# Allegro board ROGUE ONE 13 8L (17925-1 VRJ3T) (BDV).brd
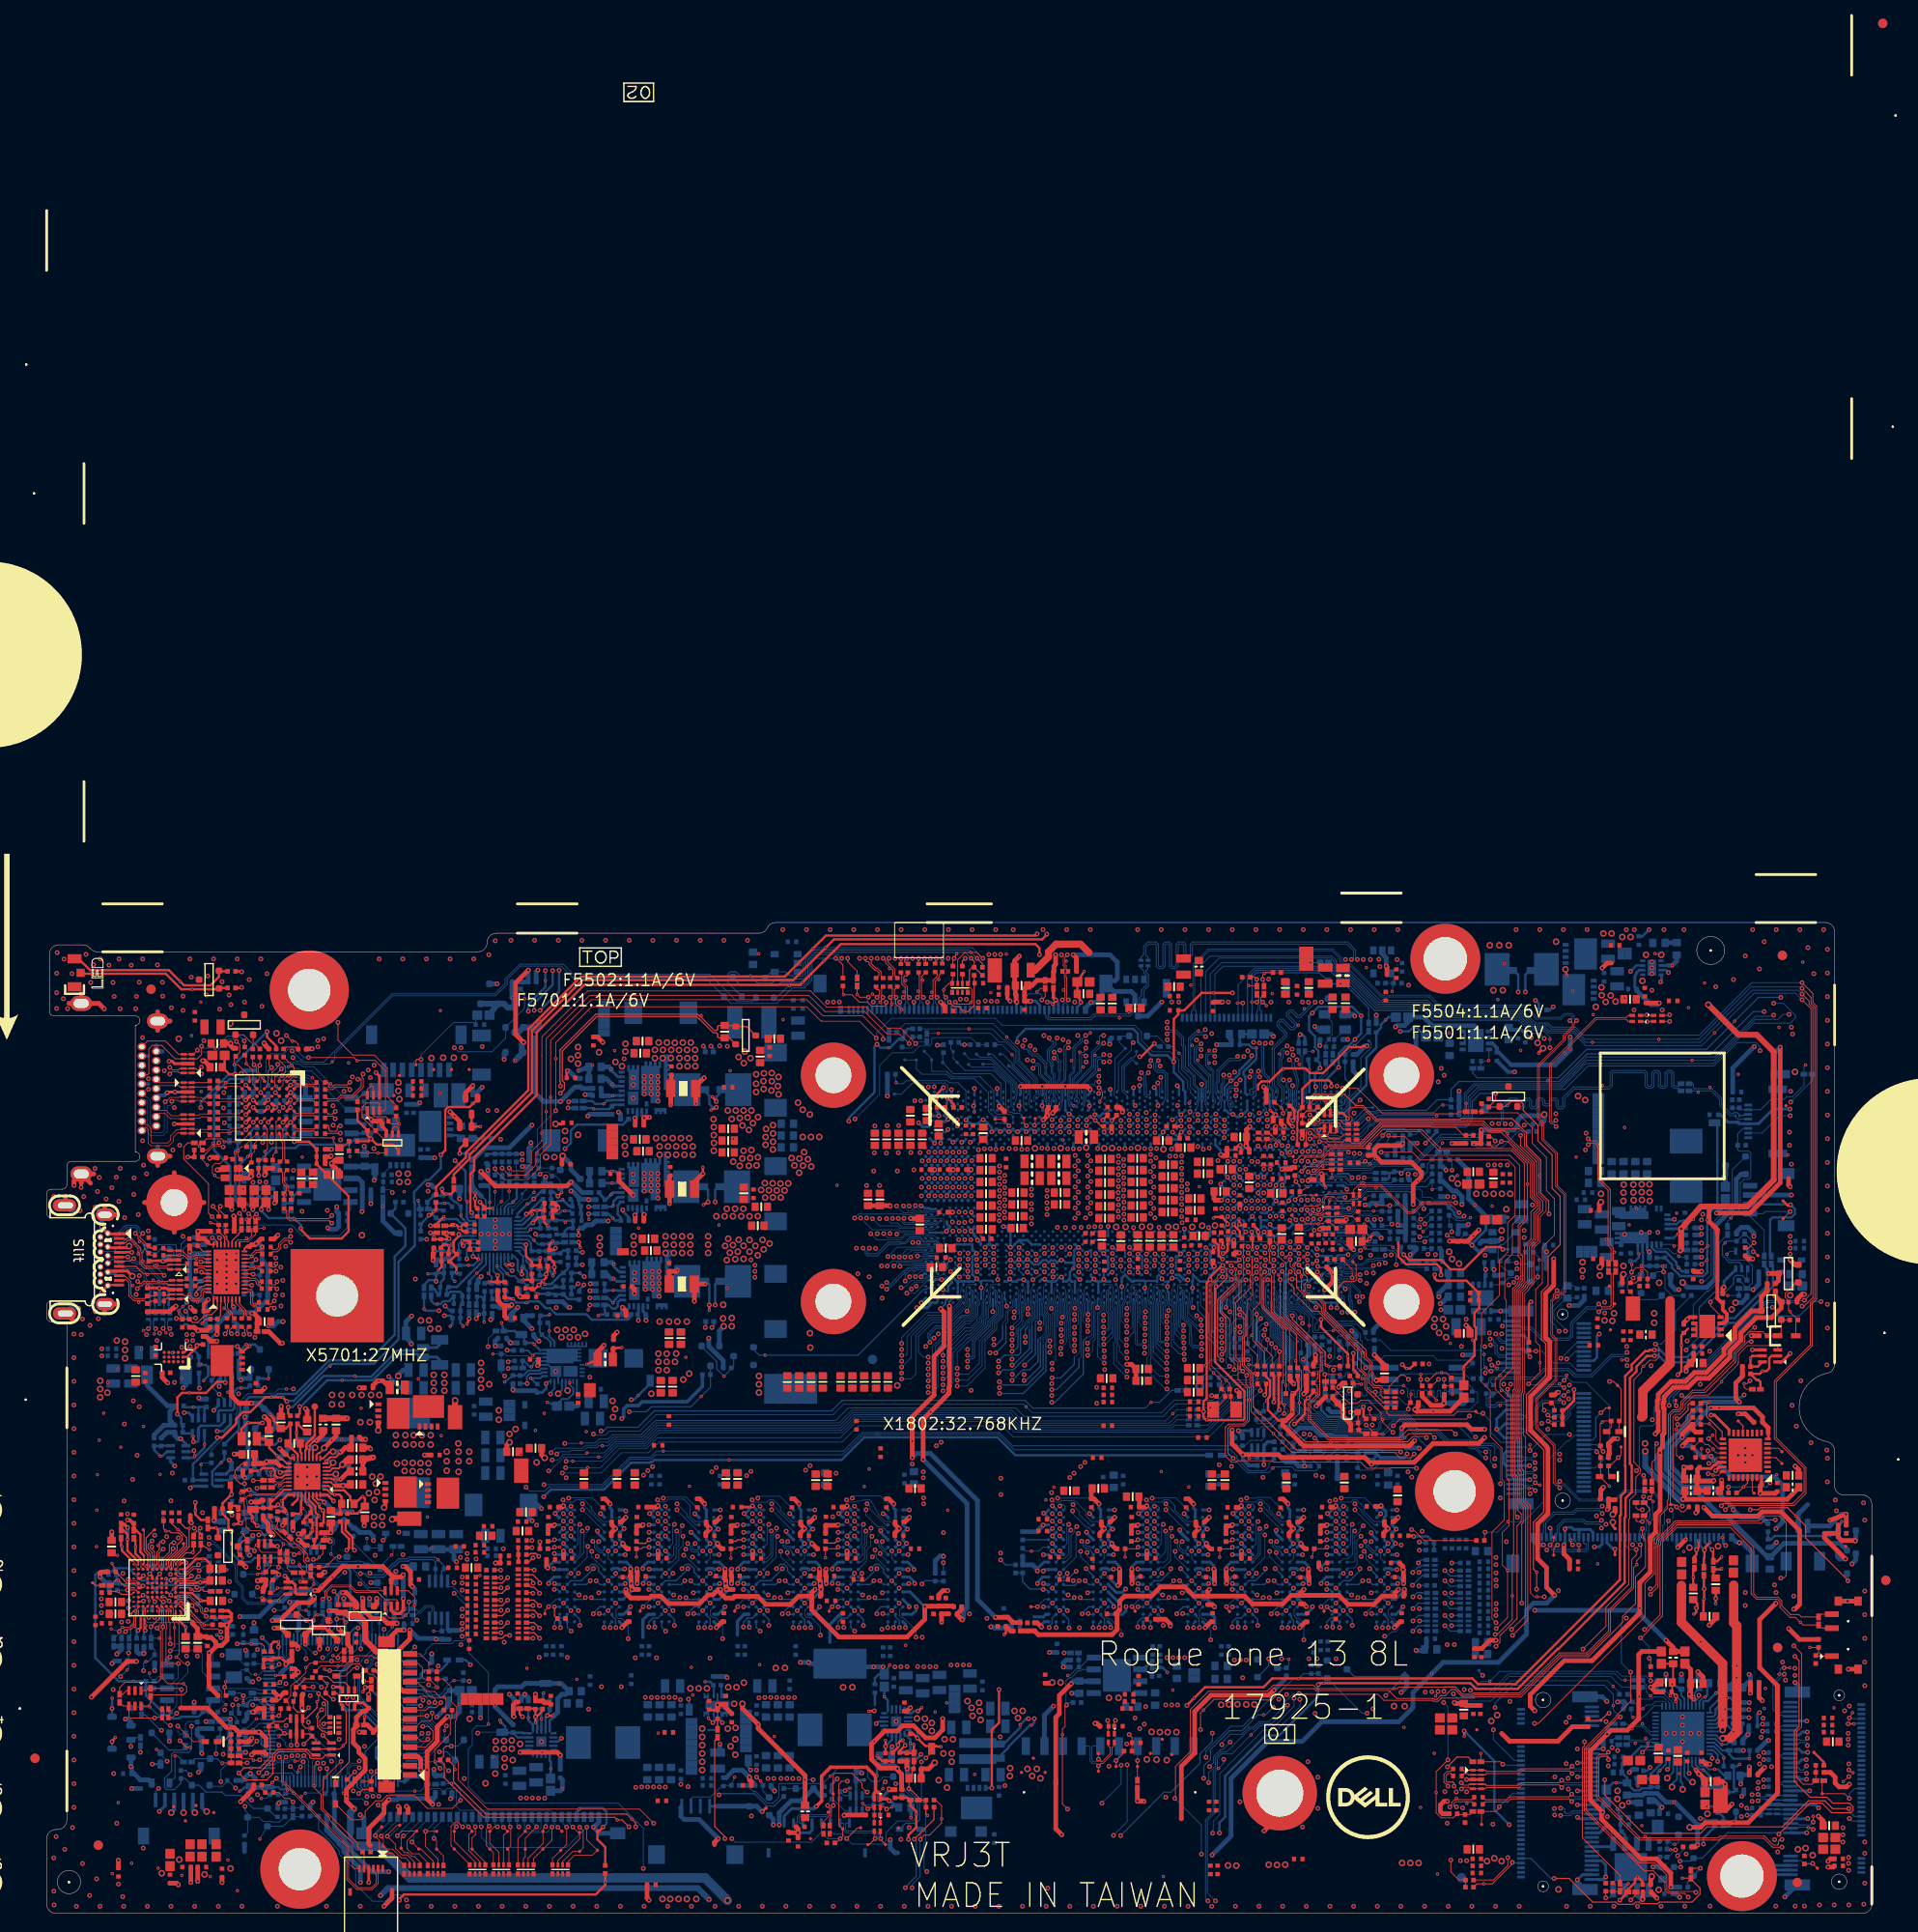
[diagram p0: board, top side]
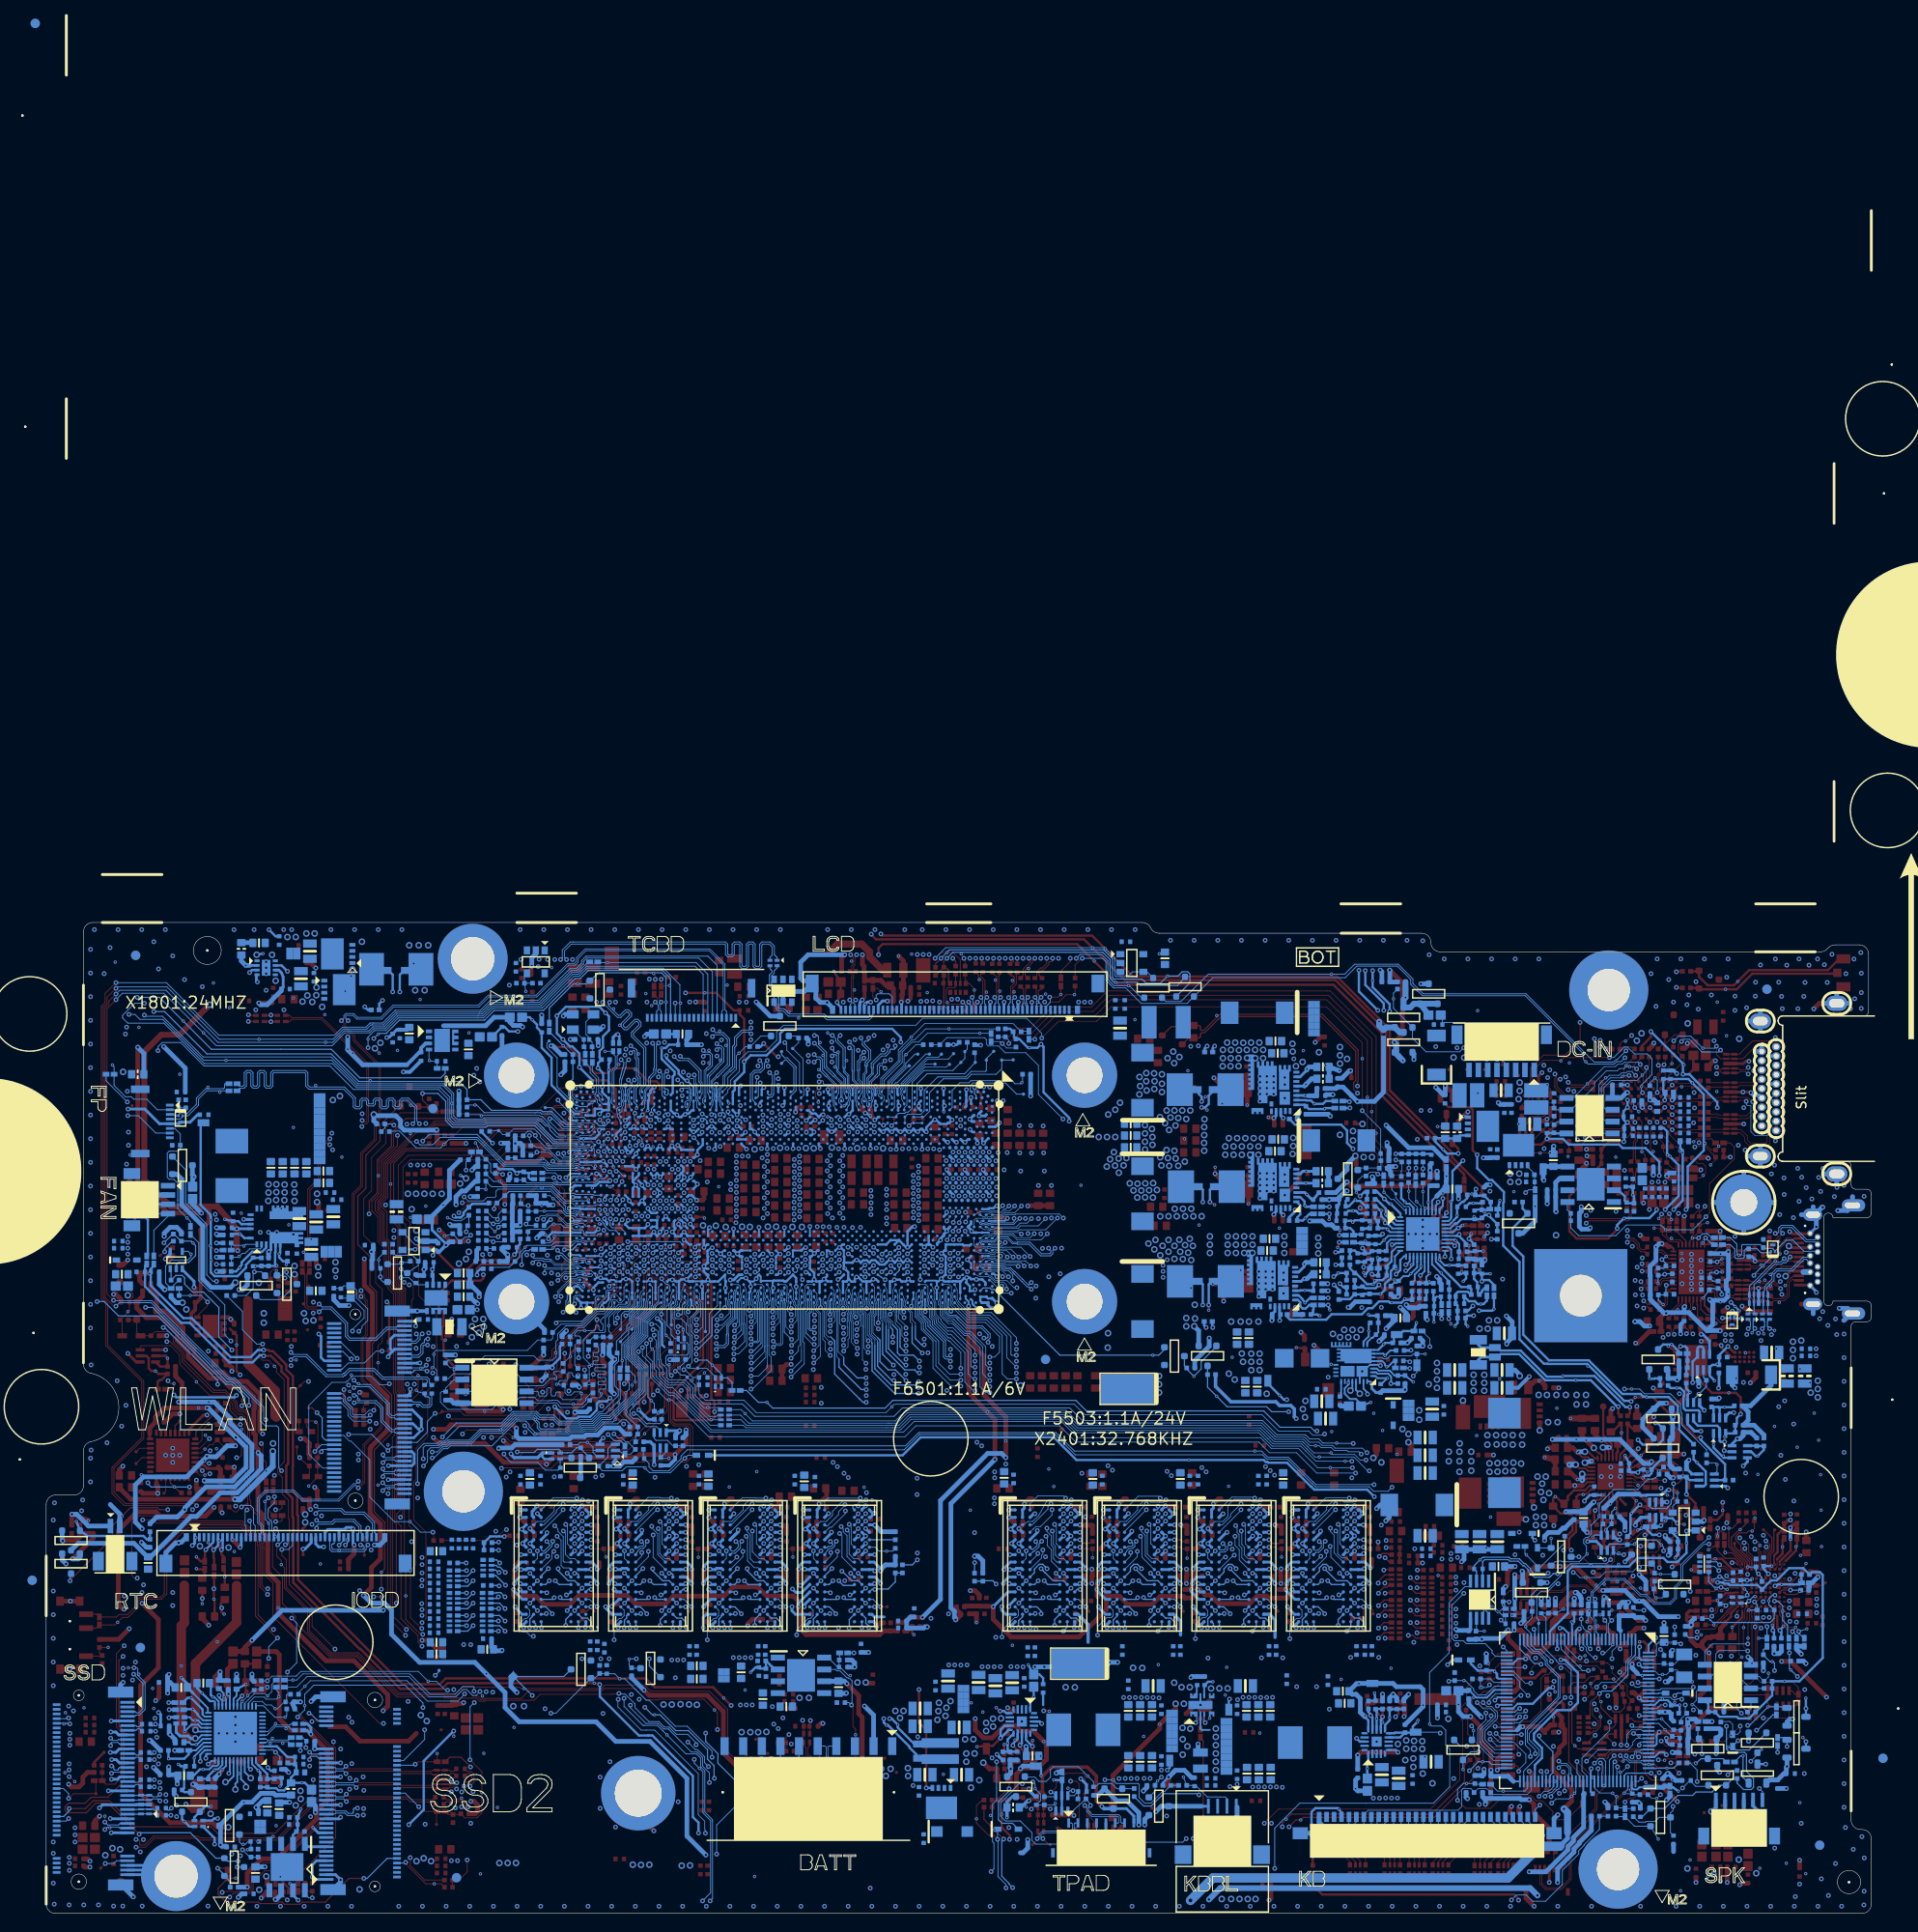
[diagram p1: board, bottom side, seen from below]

Outline 196 x 106.35 mm; copper layers: TOP, L2SGND, L3SGND, L4SGND, L5GND, L6, L7GND, BOTTOM. Coordinates in mm from the lower left corner of the outline.
Outline path: 0,77.22 0,75.16 arc(0.15,74.81) 0.5,74.67 4.12,74.67 arc(4.62,75.17) 5.12,74.67 5.12,65.72 arc(4.62,65.22) 4.12,65.72 0.5,65.72 arc(0.15,65.57) 0,65.22 0,64 arc(0.15,63.65) 0.5,63.5 1.67,63.5 arc(2.02,63.35) 2.17,63 2.17,10 arc(1.88,9.29) 1.17,9 1,9 arc(0.29,8.71) 0,8 0,1 arc(0.29,0.29) 1,0 195,0 arc(195.71,0.29) 196,1 196,43.9 arc(195.71,44.61) 195,44.9 193,44.9 arc(192.29,45.19) 192,45.9 192,49.65 arc(191.77,50.28) 191.2,50.63 arc(188.2,54.3) 191.2,57.97 arc(191.77,58.32) 192,58.95 192,105.35 arc(191.71,106.06) 191,106.35 78.3,106.35 arc(77.76,106.19) 77.39,105.77 arc(77.03,105.36) 76.49,105.2 48.3,105.2 arc(47.59,104.91) 47.3,104.2 arc(47.01,103.49) 46.3,103.2 5.46,103.2 arc(5.08,103.28) 4.76,103.49 4.59,103.66 arc(4.27,103.87) 3.89,103.95 1.3,103.95 arc(0.59,103.66) 0.3,102.95 0.3,96.82 arc(0.45,96.47) 0.8,96.32 9.52,96.32 arc(10.02,95.82) 9.52,95.32 9.52,81.72 arc(10.02,81.22) 9.52,80.72 2.67,80.72 arc(2.32,80.57) 2.17,80.22 2.17,78.22 arc(2.02,77.87) 1.67,77.72 0.5,77.72 arc(0.15,77.57) 0,77.22 ; 1.15,3.35 arc(2.4,4.6) 3.65,3.35 arc(2.4,2.1) 1.15,3.35 ; 1.52,76.29 2.52,76.29 arc(2.82,75.99) 2.52,75.69 1.52,75.69 arc(1.22,75.99) 1.52,76.29 ; 1.52,64.69 2.52,64.69 arc(2.82,64.39) 2.52,64.09 1.52,64.09 arc(1.22,64.39) 1.52,64.69 ; 3.37,98.12 4.07,98.12 arc(4.52,97.67) 4.07,97.22 3.37,97.22 arc(2.92,97.67) 3.37,98.12 ; 3.37,79.82 4.07,79.82 arc(4.52,79.37) 4.07,78.92 3.37,78.92 arc(2.92,79.37) 3.37,79.82 ; 5.82,75.29 6.67,75.29 arc(6.97,74.99) 6.67,74.69 5.82,74.69 arc(5.52,74.99) 5.82,75.29 ; 5.82,65.69 6.67,65.69 arc(6.97,65.39) 6.67,65.09 5.82,65.09 arc(5.52,65.39) 5.82,65.69 ; 12.28,76.3 arc(13.7,77.73) 15.13,76.3 arc(13.7,74.88) 12.28,76.3 ; 24.95,4.75 arc(27.2,7) 29.45,4.75 arc(27.2,2.5) 24.95,4.75 ; 25.95,99.1 arc(28.2,101.35) 30.45,99.1 arc(28.2,96.85) 25.95,99.1 ; 28.95,66.3 arc(31.2,68.55) 33.45,66.3 arc(31.2,64.05) 28.95,66.3 ; 82.59,89.96 arc(84.49,91.86) 86.39,89.96 arc(84.49,88.06) 82.59,89.96 ; 82.59,65.66 arc(84.49,67.56) 86.39,65.66 arc(84.49,63.76) 82.59,65.66 ; 129.92,12.9 arc(132.42,15.4) 134.92,12.9 arc(132.42,10.4) 129.92,12.9 ; 143.59,89.96 arc(145.49,91.86) 147.39,89.96 arc(145.49,88.06) 143.59,89.96 ; 143.59,65.66 arc(145.49,67.56) 147.39,65.66 arc(145.49,63.76) 143.59,65.66 ; 147.9,102.46 arc(150.2,104.76) 152.5,102.46 arc(150.2,100.16) 147.9,102.46 ; 148.95,45.3 arc(151.2,47.55) 153.45,45.3 arc(151.2,43.05) 148.95,45.3 ; 159.88,22.9 arc(160.7,23.73) 161.53,22.9 arc(160.7,22.08) 159.88,22.9 ; 160.13,2.9 arc(160.7,3.47) 161.28,2.9 arc(160.7,2.33) 160.13,2.9 ; 161.98,44.3 arc(162.8,45.13) 163.63,44.3 arc(162.8,43.48) 161.98,44.3 ; 162.23,64.3 arc(162.8,64.88) 163.38,64.3 arc(162.8,63.73) 162.23,64.3 ; 177.2,103.35 arc(178.7,104.85) 180.2,103.35 arc(178.7,101.85) 177.2,103.35 ; 179.75,4 arc(182.05,6.3) 184.35,4 arc(182.05,1.7) 179.75,4 ; 192.5,23.98 arc(193.08,23.4) 192.5,22.82 arc(191.92,23.4) 192.5,23.98 ; 192.5,4.23 arc(193.32,3.4) 192.5,2.58 arc(191.68,3.4) 192.5,4.23

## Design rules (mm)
constraint set DEFAULT: min track width 0.127, pair gap 0.102
net group CLK_50-MWS: nets SUS_CLK SUSCLK_WLAN
net group DDR4_A_BA_40-MW: nets M_A_BA0 M_A_BA1
net group DDR4_A_ODT10-MW: nets M_A_CS#0 M_A_ODT0
net group DDR4_B_BA_40-MW: nets M_B_BA0 M_B_BA1
net group DDR4_B_ODT10-MW: nets M_B_CS#0 M_B_ODT0
net group DDR4_CKE_40-MW: nets M_A_CKE0 M_B_CKE0
net group DDR4_CLK: nets M_A_CLK M_B_CLK
net group DDR4_REST: nets SM_DRAMRST# SM_DRAMRST#_CPU
net group DDR4_VREF_20: nets M_VREF_CA_DIMMA M_VREF_CA_DIMMB
net group DDR4_VREF_CNT_20: nets V_SM_VREF_CNTA V_SM_VREF_CNTB
net group GND: nets EC_AGND MIC_GND
net group POWER_40M: nets 3D3V_TPM FP_3D3V
net group POWER_40M_POWER: nets PWR_CHG_UGATE1 PWR_VCORE_VIN
net group SPI_CLK_50: nets SPI_CLK_HDMI SPI_CLK_PD
net group TESTPD_4MIL: nets CPU_D4_TP CPU_D6_TP
net group TPM_5MIL: nets TPM_GPIO0 TPM_GPIO4
net group USB_OC: nets USB_OC0# USB_OC1#
net group XTAL_20MIL: nets CLKIN_XTAL_LCP PULSAR_38P4M_REFCLK
net group 65982DC: nets 65982D_DBG_CTL1 65982D_DBG_CTL2 65982D_DEBUG1 65982D_DEBUG2 65982D_DIG_AUD_N 65982D_DIG_AUD_P 65982D_GPIO1 65982D_GPIO2 65982D_GPIO3 65982D_GPIO8 65982D_HPD_CON 65982D_HRESET 65982D_I2C_ADDR 65982D_LSRX 65982D_LSTX 65982D_MRESET 65982D_RESET_N 65982D_ROSC 65982D_SBU1_R 65982D_SBU2_R 65982D_UART_RX CAD_SNK DP1_HPD_CPU DP1_HPD_CPU_R DPEQ0_A1 DPEQ1 EQ0 EQ1 HPDIN I2CEN MUX_HPD_CON PD_IRQ1 PD_OVP_TRIP_P1 PQ4417_D PQ4418_2 PQ4418_5 PQ4418_6 SSEQ0_A0 SSEQ1 TP_65982D_RESET_N TYPEC_DCIN1_EN# UPD1_ALERT_R UPD1_SMBINT# VBUS_P_CTRL
net group ASYN_50: nets BPM_CPU_N0 BPM_CPU_N1 BPM_CPU_N2 BPM_CPU_N3 H_CPUPWRGD PCH_PLTRST# PM_RSMRST# THERMTRIP#_CPU VCCST_PWRGD VCCST_PWRGD_R XDP_DBRESET#
net group AUDIO_12MIL: nets CPVEE
net group AUDIO_BEEP_10MIL: nets AUD_HP1_JACK_L1 AUD_HP1_JACK_R1 AUD_HPJD_N AUD_HPOUT_L AUD_HPOUT_R AUD_PC_BEEP_C AUD_PC_BEEP_R AUD_SENSE_A AUD_VREF CBN CBP HDA_SPKR_R JACK_PLUG KBC_BEEP_R LINE1-L_C LINE1-L_R LINE1_L LINE1_R MIC2_VREFO_L MIC2_VREFO_R SPKR
net group AUDIO_DIGITAL_50-MWS: nets HDA_RST_N_CPU
net group CHGR_PSYS_IMVP: nets CHGR_PSYS_IMVP
net group CNV: nets CNV_WT_RCOMP
net group COMP_20MIL: nets CFG_RCOMP EMMC_RCOMP SD_RCOMP XCLK_BIASREF
net group CPU_50: nets PQ4416_3 PROCHOT PROCHOT#_CPU
net group CPU_50-MWS: nets PQ4405_3 PQ4418_3 PROCHOT#_CPU_R PWR_CHG_PROCHOT# PWR_CHG_PROCHOT#_R
net group DDR4_A_BG_40-MW: nets M_A_BG0 M_A_BG1 M_A_BG1_E9_1 M_A_BG1_E9_2 M_A_BG1_E9_3 M_A_BG1_E9_4 M_A_BG1_M9_R M_B_BG1 M_B_BG1_E9_1 M_B_BG1_E9_2 M_B_BG1_E9_3 M_B_BG1_E9_4 M_B_BG1_M9_R
net group DDR4_A_CMD_40-MW: nets M_A_A0 M_A_A1 M_A_A2 M_A_A3 M_A_A4 M_A_A5 M_A_A6 M_A_A7 M_A_A8 M_A_A9 M_A_A10 M_A_A11 M_A_A12 M_A_A13 M_A_A14 M_A_A15 M_A_A16 M_A_ACT_N M_A_ALERT_N M_A_PARITY
net group DDR4_A_DATA_00_50-MW: nets M_A_DQ0 M_A_DQ1 M_A_DQ2 M_A_DQ3 M_A_DQ4 M_A_DQ5 M_A_DQ6 M_A_DQ7
net group DDR4_A_DATA_01_50-MW: nets M_A_DQ8 M_A_DQ9 M_A_DQ10 M_A_DQ11 M_A_DQ12 M_A_DQ13 M_A_DQ14 M_A_DQ15
net group DDR4_A_DATA_02_50-MW: nets M_A_DQ16 M_A_DQ17 M_A_DQ18 M_A_DQ19 M_A_DQ20 M_A_DQ21 M_A_DQ22 M_A_DQ23
net group DDR4_A_DATA_03_50-MW: nets M_A_DQ24 M_A_DQ25 M_A_DQ26 M_A_DQ27 M_A_DQ28 M_A_DQ29 M_A_DQ30 M_A_DQ31
net group DDR4_A_DATA_04_50--MW: nets M_A_DQ32 M_A_DQ33 M_A_DQ34 M_A_DQ35 M_A_DQ36 M_A_DQ37 M_A_DQ38 M_A_DQ39
net group DDR4_A_DATA_05_50-MW: nets M_A_DQ40 M_A_DQ41 M_A_DQ42 M_A_DQ43 M_A_DQ44 M_A_DQ45 M_A_DQ46 M_A_DQ47
net group DDR4_A_DATA_06_50-MW: nets M_A_DQ48 M_A_DQ49 M_A_DQ50 M_A_DQ51 M_A_DQ52 M_A_DQ53 M_A_DQ54 M_A_DQ55
net group DDR4_A_DATA_07_50-MW: nets M_A_DQ56 M_A_DQ57 M_A_DQ58 M_A_DQ59 M_A_DQ60 M_A_DQ61 M_A_DQ62 M_A_DQ63
net group DDR4_B_BG_40-MW: nets M_B_BG0
net group DDR4_B_CMD_40-MW: nets M_B_A0 M_B_A1 M_B_A2 M_B_A3 M_B_A4 M_B_A5 M_B_A6 M_B_A7 M_B_A8 M_B_A9 M_B_A10 M_B_A11 M_B_A12 M_B_A13 M_B_A14 M_B_A15 M_B_A16 M_B_ACT_N M_B_ALERT_N M_B_PARITY
net group DDR4_B_DATA_00_50-MW: nets M_B_DQ0 M_B_DQ1 M_B_DQ2 M_B_DQ3 M_B_DQ4 M_B_DQ5 M_B_DQ6 M_B_DQ7
net group DDR4_B_DATA_01_50-MW: nets M_B_DQ8 M_B_DQ9 M_B_DQ10 M_B_DQ11 M_B_DQ12 M_B_DQ13 M_B_DQ14 M_B_DQ15
net group DDR4_B_DATA_02_50-MW: nets M_B_DQ16 M_B_DQ17 M_B_DQ18 M_B_DQ19 M_B_DQ20 M_B_DQ21 M_B_DQ22 M_B_DQ23
net group DDR4_B_DATA_03_50-MW: nets M_B_DQ24 M_B_DQ25 M_B_DQ26 M_B_DQ27 M_B_DQ28 M_B_DQ29 M_B_DQ30 M_B_DQ31
net group DDR4_B_DATA_04_50-MW: nets M_B_DQ32 M_B_DQ33 M_B_DQ34 M_B_DQ35 M_B_DQ36 M_B_DQ37 M_B_DQ38 M_B_DQ39
net group DDR4_B_DATA_05_50-MW: nets M_B_DQ40 M_B_DQ41 M_B_DQ42 M_B_DQ43 M_B_DQ44 M_B_DQ45 M_B_DQ46 M_B_DQ47
net group DDR4_B_DATA_06_50-MW: nets M_B_DQ48 M_B_DQ49 M_B_DQ50 M_B_DQ51 M_B_DQ52 M_B_DQ53 M_B_DQ54 M_B_DQ55
net group DDR4_B_DATA_07_50-MW: nets M_B_DQ56 M_B_DQ57 M_B_DQ58 M_B_DQ59 M_B_DQ60 M_B_DQ61 M_B_DQ62 M_B_DQ63
net group DDR_VREF_40: nets PWR_VDDQ_VTTREF
net group ESPI_50_U: nets ESPI_ALERT#
net group FAN_TACH: nets BEEP FAN1_PWM FAN1_TACH FAN_TACH1 FAN_TACH1_C
net group KBC: nets KSI0 KSI1 KSI2 KSI3 KSI4 KSI5 KSI6 KSI7 KSO0 KSO1 KSO2 KSO3 KSO4 KSO5 KSO6 KSO7 KSO8 KSO9 KSO10 KSO11 KSO12 KSO13 KSO14 KSO15 KSO16
net group LCD_BKLT: nets BKLT_CTRL L_BKLT_CTRL LCD_BRIGHTNESS
net group LED: nets BAT1_LED# BAT2_LED# BATT_WHITE_LED# BATT_WHITE_LED_R# CAP_LED# CAP_LED#_R CAP_LED_R# CHG_AMBER_LED# CHG_AMBER_LED_R# M2_PCIE_LED2# M2_PCIE_LED# MASK_BASE_LEDS# PCH_SATA_LED# SATA_PCIE_LED# SYS_LED_MASK# SYS_LED_MASK#_R
net group LED_10MIL: nets AMBER_LED_BAT BAT_AMBER BAT_WHITE CAP_LED CAP_LED_Q WHITE_LED_BAT
net group OTHER-4MIL: nets 1D8V_EN# 1D8V_EN_R# 3D3V_LDO_SET 3V_5V_DSW_OK AC_PRESENT AD_IA AUX_EN_WOWL AUX_EN_WOWL_R BKLT_IN_EC BLON_OUT_C BLUETOOTH_EN BLUETOOTH_EN_R BT_PCMFRM_RSTN BT_PCMOUT_CLKREQ0 CLK_PCIE_PEG_REQ# CPU_DP_HPD_P CPU_SMB_ALERT# CPU_SMB_ALERT#_P0 CPU_SMB_ALERT#_P1 DBC_EN_R DBC_PANEL_EN DIAGLOOP DVSS EDP_HPD_CON EDP_HPD_CPU FAN_PWM1_C FFS_INT2 FP_EN# FPR_PWRBTN# FPR_SCAN# GPD11/LANPHYPC GPD_7 GPP_B22_GSPI1_MOSI GPP_E1/SATAXPCIE1/SATAGP1 GPP_E3/CPU_GP0 GPP_E23_STRAP GPP_H1_SFRM GPP_H2_CLKREQ0 GPP_H17_STRAP GPP_H21 GPP_H23 GSEN2_INT1_ISH GSEN2_INT2 GSEN2_INT2_ISH GSEN_INT1 GSEN_INT2 GYRO_DRDY_ISH GYRO_INT_C GYRO_INT_ISH HDMI_CEC HDMI_CEC_CON HDMI_HPD_ALS HDMI_HPD_CON HDMI_HPD_CPU HOST_DEBUG_TX HOST_DEBUG_TX_CON I_ADP ICSP_CLR INPUT3VSEL IST_TRIG JIO3_PCIE_WAKE# KB_DISABLE_CPU_R KB_LED_BL_DET KB_LED_DET_C KB_LED_PWM KBC_PWRBTN# L_BKLT_EN LCD_TST_C M2_OPT_PEDET M2_SSD_PEDET MASK_SATA_LED# ME_FWP ME_FWP_SW MESW1_B MSATA_DEVSLP_R NB_MODE# NB_MUTE# NC_THERMAL_T8 NC_U3_PD#_EC NRB_BIT OPT_CLKREQ_CPU_N OPT_DEVSLP OPT_DEVSLP_R OPT_RST# PBAT_PRES1# PBAT_PRES# PCB_ID PCB_ID1 PCB_ID2 PCH_BATLOW# PD4403_A PD4403_K PIRQA# PROJECT_ID0 PROJECT_ID1 PROJECT_ID2 PROJECT_ID3 PS175_CEC_EN PS175_GPIO0 PS175_GPIO2 PS175_PD# PS175_RST# PS_ID_R PS_ID_R1 PWR_CHG_BATGONE_L Q5705_2 Q5705_5_6 REXT RTC_3P3_EN_G SD_READ_MODE# SDRAM_ID0 SDRAM_ID1 SDRAM_ID2 SDRAM_ID3 SDRAM_ID4 SIO_EXT_SMI# SIO_EXT_WAKE# SIO_PWRBTN# SKTOCC# SKU_ID SM_INTRUDER# SPK_ID SSD_CLKREQ_CPU_N SSD_DEVSLP SSD_SCP# SSD_SCP#_1 SSD_SCP#_2 SYS_PRES1# SYSPWR_PRES TEST_MODE_1 TEST_MODE_2 TEST_MODE_3 TEST_MODE_4 TEST_MODE_5 TEST_MODE_6 TEST_MODE_7 TEST_MODE_8 TOUCH_DETECT TOUCH_DETECT_R TP_TPM_GPIO1 TP_TPM_GPIO3 TP_TPM_PP TP_WAKE_KBC# TPM_ID TPM_SPI_IRQ# U3_PD#_EC U5703_OUT USB2_ID USB2_VBUSSENSE USB_EN# USB_OC2# USB_OC3# V0.85A_VID0 V0.85A_VID1 VCCDSW_ON VCREF0 VR_RDY VRALERT# VRAM_ID1 VRAM_ID2 WIFI_RF_EN WIFI_RF_EN_R WLAN_CLKREQ_CPU_N WLAN_EN# WLAN_EN_R#
net group PECI_SVID: nets PECI_CPU
net group PECI_SVID-MW: nets H_PECI
net group PLATFORM: nets 1D0V_S5_EN 1D0V_S5_PWRGD 1D2V_HDMI_EN 1D2V_HDMI_EN_R 1D8V_S5_EN 2D5V_S3_EN 2D5V_S3_PWRGD 3V_5V_PWRGD +SDC_IN_SW +SDC_IN_SW_R1 A_ZQ_RAM1 A_ZQ_RAM2 A_ZQ_RAM3 A_ZQ_RAM4 B_ZQ_RAM1 B_ZQ_RAM2 B_ZQ_RAM3 B_ZQ_RAM4 CLKRUN# EDP_VDD_EN FFS_INT1 FPR_CL_SIO# GSEN2_INT1 GSEN2_INT1_C GSEN2_INT2_C GYRO_DRDY IC_DELAY IR_CAM_DET# ISH_KB_DISABLE ITP_PMODE KB_DET# LAN_WAKE# LCD_TST LCD_VCC_TEST_EN LID_CL_SIO# LID_CL_SIO_TAB# LVDS_VDD_EN_R ME_SUS_PWR_ACK_R MEM_CHA_EN MEM_CHB_EN NC_EC_SLP_S0IX# PCH_RSMRST# PCIE_WAKE#_CPU PM_RSMRST#_M POWER_SW_IN# PQ4405_2 PQ4405_5 PQ4405_6 PQ4408_C PQ4408_E PRIM_PWRGD PTP_DIS# PWR_1D0V_PG PWR_VDDQ_EN RSMRST_PWRGD# RTCRST_ON SRTC_RST# SUSACK#_R TOUCH_REPORT_SW TP_ON#_GATE VCCSTG_EN_L1 VCCSTG_EN_R1 VCCSTU_EN_R VR_EN
net group POWER_10M: nets 1D0V_VCCA_XTAL 1D0V_VCCAMPHYPLL 1D0V_VCCDSW 1D2V_HDMI_VDDA 1D2V_HDMI_VDDRX 1D24V_VCCDPHY 1D24V_VCCDPHY_EC 1V_VCCST_CPU 1V_VCCSTG 3D3V_1D8V_AVDD 3D3V_1D8V_AVDD_IO 3D3V_FLASH 3D3V_RTC_SYS 3D3V_TBT 3D3V_VCCPRTC 3V5V_CT1 3V5V_CT2 3V_S5_EN 5V_S5_EN 65982D_BUSPWR 65982D_GND 65982D_LDO_1V8A 65982D_LDO_1V8D 65982D_LDO_BMC AC_DIS AC_IN# AUDIO_47 AUX_MODE DC_IN_OFF HVA_GATE1 HVA_GATE2 HW_ACAV_IN HW_ACAVIN_NB I_BATT LDO1_CAP LDO2_CAP LDO3_CAP LPS_SW LPS_SW_A LPS_SW_B LPS_SW_C LPS_SW_D MIC_CAP PD_VBUS_C_CTRL1 PD_VBUS_C_CTRL1_A PD_VBUS_C_CTRL1_R PD_VBUS_C_EN PD_VBUS_C_EN_A PQ4415_5 PQ4415_6 PQ4417_G PRD_CC1 PRD_CC2 PU4348_G PWR_1D0V_BT PWR_1D0V_FB_A PWR_1D0V_PFM PWR_1D0V_SS PWR_1D0V_TON PWR_3D3V_FB PWR_3D3V_VOUT PWR_5V_FB PWR_5V_FB_A PWR_5V_VOUT PWR_CHG_ACIN PWR_CHG_ACOK PWR_CHG_AIN PWR_CHG_AMON PWR_CHG_ASGATE PWR_CHG_BATGONE PWR_CHG_BGATE PWR_CHG_COMP PWR_CHG_COMP_R PWR_CHG_CSIN PWR_CHG_CSIN_R PWR_CHG_CSIP PWR_CHG_CSIP_R PWR_CHG_CSON PWR_CHG_CSON_R PWR_CHG_CSOP PWR_CHG_CSOP_R PWR_CHG_DCIN PWR_CHG_DCIN_R PWR_CHG_OTGEN PWR_CHG_OTGPG PWR_CHG_PROG PWR_VCCGT_COMP PWR_VCCGT_COMP1 PWR_VCCGT_FB PWR_VCCGT_FB1 PWR_VCCGT_FB2 PWR_VCCGT_FB_RC PWR_VCCGT_FCCM# PWR_VCCGT_FCCM#_RA PWR_VCCGT_FCCM#_RB PWR_VCCGT_IMON PWR_VCCGT_ISEN1 PWR_VCCGT_ISEN2 PWR_VCCGT_ISUMN PWR_VCCGT_ISUMN_GA PWR_VCCGT_ISUMN_GB PWR_VCCGT_ISUMN_P_1 PWR_VCCGT_ISUMN_P_2 PWR_VCCGT_ISUMN_RC PWR_VCCGT_ISUMNB PWR_VCCGT_ISUMP PWR_VCCGT_ISUMP_GA PWR_VCCGT_ISUMP_GB PWR_VCCGT_NTC PWR_VCCGT_NTC1 PWR_VCCGT_PWMA PWR_VCCGT_PWMA_RA PWR_VCCGT_PWMB PWR_VCCGT_PWMB_RA PWR_VCCGT_RTN PWR_VCCSA_COMP PWR_VCCSA_COMP_RC PWR_VCCSA_FB PWR_VCCSA_FB1 PWR_VCCSA_FB2 PWR_VCCSA_FB_RC PWR_VCCSA_FCCM PWR_VCCSA_IMON PWR_VCCSA_ISUMN PWR_VCCSA_ISUMN_P_1 PWR_VCCSA_ISUMN_P_2 PWR_VCCSA_ISUMN_R PWR_VCCSA_ISUMN_RC PWR_VCCSA_ISUMNB PWR_VCCSA_ISUMP PWR_VCCSA_ISUMP_R PWR_VCCSA_RTN PWR_VCORE_COMP PWR_VCORE_COMP1 PWR_VCORE_FB PWR_VCORE_FB1 PWR_VCORE_FB2 PWR_VCORE_FB_RC PWR_VCORE_FCCM# PWR_VCORE_FCCM#_R PWR_VCORE_IMON PWR_VCORE_ISUMN PWR_VCORE_ISUMN_G PWR_VCORE_ISUMN_P_1 PWR_VCORE_ISUMN_P_2 PWR_VCORE_ISUMN_RC PWR_VCORE_ISUMNA PWR_VCORE_ISUMP PWR_VCORE_ISUMP_G PWR_VCORE_NTC PWR_VCORE_NTC1 PWR_VCORE_PROG1 PWR_VCORE_PROG2 PWR_VCORE_PWM_R PWR_VCORE_RTN PWR_VCORE_VCC_R PWR_VCORE_VRHOT# PWR_VDDQ_PG PWR_VDDQ_VCC PWR_VTT_EN Q6204_G RUNPWROK VBUS_P_CTRL_R VCCPD_VBUS_ACK VCCRTCEXT VCI_IN1# VDDQ_PWRGD
net group POWER_10M_POWER: nets 1.8V_RUN_FB 1D2V_HDMI_FB 3D3V_MIC_VCC 3V_5V_POK# 3V_5V_POK_C AC_IN#_G AD_OFF_L AD_OFF_R PWR_1D0V_FB PWR_1D8V_POK PWR_2D5V_FB PWR_3D3V_EN PWR_3D3V_FB2 PWR_3V_PG PWR_5V_EN PWR_5V_EN1_R PWR_5V_PG PWR_VCCSA_PWM PWR_VCORE_PWM PWR_VDDQ_FB PWR_VDDQ_VDDQ
net group POWER_15M: nets Q6205_Q USB1_CC1 USB1_CC2
net group POWER_20M: nets 1D8V_S0 1D8V_S5_KBC 1V_VREF_CPU 3D3V_AUX_KBC 3D3V_AUX_S5 3D3V_CAMERA_S0 3D3V_ECVBAT 3D3V_RTC 5V_AUX_S5 +5V_AVDD +RTC_VCC +V_VREF_PATH1 +V_VREF_PATH2 PQ4348_D PWR_3D3V_BOOT PWR_3D3V_BOOT_A PWR_5V_BOOT PWR_5V_BOOT_A PWR_5V_LDO PWR_CHG_BOOT1 PWR_CHG_BOOT2 PWR_CHG_SNB PWR_CHG_VDDP PWR_VDDQ_CS PWR_VDDQ_SNB PWR_VDDQ_TON RTC_3P3_EN_D RTC_AUX_S5 RTC_VCC_C
net group POWER_20M_POWER: nets 1D8V_CPVDD KB_BL_CTRL# PWR_VCCGT_BOOTA PWR_VCCGT_BOOTA_RC PWR_VCCGT_BOOTB PWR_VCCGT_BOOTB_RC PWR_VCCGT_SNB1 PWR_VCCGT_SNB2 PWR_VCCGT_VCCDA PWR_VCCGT_VCCDB PWR_VCCSA_BST PWR_VCCSA_BST_RC PWR_VCORE_BOOT PWR_VCORE_BOOT_RC PWR_VCORE_SNB PWR_VCORE_VCC PWR_VDDQ_BOOT PWR_VDDQ_BOOTA PWR_VDDQ_BOOTB
net group POWER_25M: nets PQ3802_1 PS_ID PS_ID_R2 PSID_DISABLE#_R_C
net group POWER_25M_POWER: nets PWR_CHG_BT1_R PWR_CHG_BT2_R PWR_CHG_LGATE1 PWR_CHG_LGATE2 PWR_CHG_UGATE2 PWR_VCCGT_BOOTRA PWR_VCCGT_BOOTRB PWR_VCORE_BOOTR
net group POWER_160M: nets VDD
net group POWER_320M_POWER: nets PWR_CHG_VBAT1
net group REF10M: nets VR_CAP
net group RESET_SIGNAL: nets 3V5V_S0_ON 3V_5V_EN ACOK# ALWON EXT_PWR_GATE# GPPC_H18_BOOTMPC GPPC_H18_VCCIO_LPM NC_SIO_SLP_S4#_EC PANEL_BKEN PANEL_BKEN_EC PCH_DPWROK PLT_RST#_Q_TPM2 PLTRST#_CPU PM_PCH_PWROK PM_SLP_A# PM_SLP_S0# PM_SLP_S3# PM_SLP_S4# PM_SLP_S5# Q502_G RESET_OUT# RTC_DET# RTC_RST# SM_PGCNTL SYS_PWROK TCH_INTR# TOUCH_PANEL_INTR# TOUCH_PANEL_PD# TP_EN# VTT_CNTL
net group SPI_50-MWS: nets SIO_EXT_SCI# SIO_RCIN# SPI_CS_HDMI SPI_CS_PD SPI_HOLD_HDMI SPI_HOLD_PD SPI_IRQ#_TPM2 SPI_SI_HDMI SPI_SI_PD SPI_SO_HDMI SPI_SO_PD SPI_WP_HDMI SPI_WP_PD
net group SVID-MW: nets SVID_ALERT#_CPU SVID_ALERT#_CPU_R SVID_ALERT#_VR SVID_CLK_CPU SVID_CLK_CPU_R SVID_CLK_VR SVID_DATA_CPU SVID_DATA_CPU_R SVID_DATA_VR
net group T8: nets CMP_VIN0 CMP_VIN0_R VD_IN1_C
net group T8-MW: nets CMP_VOUT0
net group THERM_SHUTDOWN: nets ALERT# PURE_HW_SHUTDOWN# T_CRIT# THERM_SYS_SHDN#
net group UART_MW-MW: nets UART_2_CRXD_DTXD UART_2_CRXD_DTXD_CON UART_2_CTXD_DRXD UART_2_CTXD_DRXD_CON
net group XDP_CHECK: nets CFG3 CFG4 PCH_JTAG_TCK XDP_PRDY# XDP_PREQ# XDP_TCLK XDP_TDI XDP_TDO_CPU XDP_TMS XDP_TRST#
net group XTAL-MW: nets MEC_XTAL1_R MEC_XTAL2 XTL_24M_X1_CPU XTL_24M_X1_R XTL_24M_X2_CPU XTL_24M_X2_R XTL_27M_X1_HDMI XTL_27M_X2_HDMI XTL_27M_X2_R XTL_32K_X1_CPU XTL_32K_X2_CPU
nets with their own width: min track width 0.127; nets EDP_RCOMP_CPU

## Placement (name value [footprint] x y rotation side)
AFTP2507  AFTE14P-GP  [AFTE14P-75]  193.21 39.39 0 top
AFTP2508  AFTE14P-GP  [AFTE14P-75]  190.92 40.79 0 top
AFTP2601  AFTE14P-GP  [AFTE14P-75]  186.48 76.47 270 top
AFTP2602  AFTE14P-GP  [AFTE14P-75]  186.48 74.57 270 top
AFTP2603  AFTE14P-GP  [AFTE14P-75]  187.06 78.86 270 top
AFTP2604  AFTE14P-GP  [AFTE14P-75]  186.78 86.68 270 top
AFTP2901  AFTE14P-GP  [AFTE14P-75]  16.04 11.58 0 top
AFTP2902  AFTE14P-GP  [AFTE14P-75]  17.95 10.81 0 top
AFTP2903  AFTE14P-GP  [AFTE14P-75]  13.63 11.45 270 top
AFTP2904  AFTE14P-GP  [AFTE14P-75]  14.9 9.92 270 top
AFTP4301  AFTE14P-GP  [AFTE14P-75]  37.89 89.93 0 top
AFTP4302  AFTE14P-GP  [AFTE14P-75]  37.3 87.78 0 top
AFTP4303  AFTE14P-GP  [AFTE14P-75]  41.57 90.57 0 top
AFTP4304  AFTE14P-GP  [AFTE14P-75]  39.66 91.08 0 top
AFTP4305  AFTE14P-GP  [AFTE14P-75]  43.47 90.57 0 top
AFTP4306  AFTE14P-GP  [AFTE14P-75]  120.82 17.04 0 top
AFTP4307  AFTE14P-GP  [AFTE14P-75]  119.8 18.69 0 top
AFTP4308  AFTE14P-GP  [AFTE14P-75]  118.53 17.16 0 top
AFTP4309  AFTE14P-GP  [AFTE14P-75]  114.85 15.77 0 top
AFTP4310  AFTE14P-GP  [AFTE14P-75]  112.94 17.16 0 top
AFTP4311  AFTE14P-GP  [AFTE14P-75]  112.94 15.26 0 top
AFTP4312  AFTE14P-GP  [AFTE14P-75]  107.23 15.13 180 top
AFTP4313  AFTE14P-GP  [AFTE14P-75]  105.96 16.66 0 top
AFTP4314  AFTE14P-GP  [AFTE14P-75]  104.69 15.13 180 top
AFTP4315  AFTE14P-GP  [AFTE14P-75]  117.13 15.77 0 top
AFTP4316  AFTE14P-GP  [AFTE14P-75]  45.38 90.57 0 top
AFTP5001  AFTE14P-GP  [AFTE14P-75]  168.06 102 0 top
AFTP6108  AFTE14P-GP  [AFTE14P-75]  167.81 54.25 90 top
AFTP6109  AFTE14P-GP  [AFTE14P-75]  153.48 53.87 90 top
AFTP6110  AFTE14P-GP  [AFTE14P-75]  169.08 50.06 90 top
AFTP6111  AFTE14P-GP  [AFTE14P-75]  168.38 65.42 90 top
AFTP6112  AFTE14P-GP  [AFTE14P-75]  168.7 56.66 90 top
AFTP6113  AFTE14P-GP  [AFTE14P-75]  167.93 62.63 90 top
AFTP6114  AFTE14P-GP  [AFTE14P-75]  167.81 67.33 90 top
AFTP6301  AFTE14P-GP  [AFTE14P-75]  190.67 12.85 0 top
AFTP6302  AFTE14P-GP  [AFTE14P-75]  154.09 9.54 0 top
AFTP6303  AFTE14P-GP  [AFTE14P-75]  190.16 4.84 0 top
AFTP6304  AFTE14P-GP  [AFTE14P-75]  189.78 17.29 0 top
AFTP6305  AFTE14P-GP  [AFTE14P-75]  166.92 20.72 0 top
AFTP6306  AFTE14P-GP  [AFTE14P-75]  153.58 19.7 0 top
AFTP6501  AFTE14P-GP  [AFTE14P-75]  39.97 6.9 0 top
AFTP6502  AFTE14P-GP  [AFTE14P-75]  35.98 9.29 0 top
AFTP6503  AFTE14P-GP  [AFTE14P-75]  36.16 7.21 0 top
AFTP6504  AFTE14P-GP  [AFTE14P-75]  55.33 8.81 0 top
AFTP6505  AFTE14P-GP  [AFTE14P-75]  37.91 9.47 0 top
AFTP6506  AFTE14P-GP  [AFTE14P-75]  38.06 7 0 top
AFTP6507  AFTE14P-GP  [AFTE14P-75]  49.49 6.9 0 top
AFTP6508  AFTE14P-GP  [AFTE14P-75]  39.74 8.83 0 top
AFTP6509  AFTE14P-GP  [AFTE14P-75]  41.87 8.81 0 top
AFTP6510  AFTE14P-GP  [AFTE14P-75]  43.78 8.81 0 top
AFTP6511  AFTE14P-GP  [AFTE14P-75]  47.59 8.81 0 top
AFTP6512  AFTE14P-GP  [AFTE14P-75]  41.87 6.9 0 top
AFTP6513  AFTE14P-GP  [AFTE14P-75]  49.49 8.81 0 top
AFTP6514  AFTE14P-GP  [AFTE14P-75]  43.78 6.9 0 top
AFTP6515  AFTE14P-GP  [AFTE14P-75]  45.68 8.81 0 top
AFTP6516  AFTE14P-GP  [AFTE14P-75]  59.14 6.77 0 top
AFTP6517  AFTE14P-GP  [AFTE14P-75]  45.68 6.9 0 top
AFTP6518  AFTE14P-GP  [AFTE14P-75]  47.59 6.9 0 top
AFTP6519  AFTE14P-GP  [AFTE14P-75]  57.24 6.65 0 top
AFTP6520  AFTE14P-GP  [AFTE14P-75]  51.4 8.81 0 top
AFTP6521  AFTE14P-GP  [AFTE14P-75]  53.3 8.81 0 top
AFTP6522  AFTE14P-GP  [AFTE14P-75]  55.21 6.77 0 top
AFTP6523  AFTE14P-GP  [AFTE14P-75]  57.24 8.68 0 top
AFTP6524  AFTE14P-GP  [AFTE14P-75]  51.4 6.9 0 top
AFTP6525  AFTE14P-GP  [AFTE14P-75]  91.48 9.16 0 top
AFTP6529  AFTE14P-GP  [AFTE14P-75]  71.72 7.38 180 top
AFTP6530  AFTE14P-GP  [AFTE14P-75]  77.26 11.3 180 top
AFTP6531  AFTE14P-GP  [AFTE14P-75]  82.03 8.02 0 top
AFTP6532  AFTE14P-GP  [AFTE14P-75]  90.08 7.38 270 top
AFTP6533  AFTE14P-GP  [AFTE14P-75]  88.18 7.38 270 top
AFTP6534  AFTE14P-GP  [AFTE14P-75]  84.47 12.82 180 top
AFTP6535  AFTE14P-GP  [AFTE14P-75]  83.94 10.86 180 top
AFTP6536  AFTE14P-GP  [AFTE14P-75]  85.48 9.06 0 top
AFTP6537  AFTE14P-GP  [AFTE14P-75]  87.42 9.19 0 top
AFTP6538  AFTE14P-GP  [AFTE14P-75]  59.14 8.81 0 top
AFTP6539  AFTE14P-GP  [AFTE14P-75]  53.3 6.9 0 top
AFTP6601  AFTE14P-GP  [AFTE14P-75]  161.84 40.35 0 top
AFTP6602  AFTE14P-GP  [AFTE14P-75]  161.84 38.45 0 top
AFTP6607  AFTE14P-GP  [AFTE14P-75]  168.42 38.5 0 top
AFTP6608  AFTE14P-GP  [AFTE14P-75]  168.44 41.29 0 top
AFTP6609  AFTE14P-GP  [AFTE14P-75]  174.41 43.88 0 top
BATT1  ETY-CON10-28-GP-U  [50299-01001-002-U]  114.15 13 180 bottom
BIOS1  MX25L12872FM2I-10G-GP  [SOIC8-1H86]  147.87 56.66 270 bottom
C501  SCD1U16V2KX-3DLGP  [C402H22]  138.11 55.97 0 top
C801  SC1U10V2KX-1DLGP  [C402H22]  147.05 94.68 180 bottom
C802  SC1U10V2KX-1DLGP  [C402H22]  121.07 96.92 270 top
C803  SC1U10V2KX-1DLGP  [C402H22]  125.26 70.5 180 top
C804  SC1U10V2KX-1DLGP  [C402H22]  113.96 54.88 270 top
C805  SCD1U16V2KX-3DLGP  [C402H22]  127.22 82.11 90 top
C806  SC1U10V2KX-1DLGP  [C402H22]  128.69 81.68 270 top
C1102  SC1U10V2KX-1DLGP  [C402H22]  101 72.41 90 top
C1103  SC1U10V2KX-1DLGP  [C402H22]  96.31 75.25 90 top
C1104  SC1U10V2KX-1DLGP  [C402H22]  94.4 79.82 90 top
C1105  SC1U10V2KX-1DLGP  [C402H22]  98.72 84.09 180 top
C1106  SC1U10V2KX-1DLGP  [C402H22]  98.31 79.82 90 top
C1107  SC1U10V2KX-1DLGP  [C402H22]  96.36 79.82 90 top
C1108  SC1U10V2KX-1DLGP  [C402H22]  122.16 72.08 0 top
C1109  SC1U10V2KX-1DLGP  [C402H22]  123.38 71.7 90 top
C1110  SC1U10V2KX-1DLGP  [C402H22]  112.31 72.54 0 top
C1111  SC1U10V2KX-1DLGP  [C402H22]  111.55 72.54 0 top
C1112  SC22U6D3V3MX-1-DL-GP  [C603H40]  126.66 79.86 270 top
C1113  SC22U6D3V3MX-1-DL-GP  [C603H40]  132.63 72.92 0 top
C1114  SC1U10V2KX-1DLGP  [C402H22]  128.13 76.62 0 top
C1115  SC22U6D3V3MX-1-DL-GP  [C603H40]  155.36 78.89 180 top
C1116  SC1U10V2KX-1DLGP  [C402H22]  156.38 78.89 180 top
C1117  SC1U10V2KX-1DLGP  [C402H22]  157.14 78.89 180 top
C1118  SC22U6D3V3MX-1-DL-GP  [C603H40]  166.23 79.67 270 bottom
C1119  SC1U10V2KX-1DLGP  [C402H22]  131.46 80.84 180 top
C1120  SC10U6D3V3MX-DL-GP  [C603H36]  166.23 78.4 270 bottom
C1121  SC1U10V2KX-1DLGP  [C402H22]  130.7 80.84 180 top
C1122  SC22U6D3V3MX-1-DL-GP  [C603H40]  132.12 77.28 270 top
C1123  SC10U6D3V3MX-DL-GP  [C603H36]  134.48 72.97 0 top
C1128  SC22U6D3V3MX-1-DL-GP  [C603H40]  126.02 77.49 270 top
C1129  SC22U6D3V3MX-1-DL-GP  [C603H40]  129.15 78.45 180 top
C1130  SC22U6D3V3MX-1-DL-GP  [C603H40]  123.18 57.24 90 top
C1131  SC22U6D3V3MX-1-DL-GP  [C603H40]  117.64 57.17 270 top
C1132  SC22U6D3V3MX-1-DL-GP  [C603H40]  117.64 58.44 270 top
C1133  SC22U6D3V3MX-1-DL-GP  [C603H40]  113.32 72.28 0 top
C1134  SC22U6D3V3MX-1-DL-GP  [C603H40]  152.19 62.25 90 top
C1135  SC22U6D3V3MX-1-DL-GP  [C603H40]  123.76 72.71 90 top
C1136  SC10U6D3V3MX-DL-GP  [C603H36]  123.18 55.95 90 top
C1137  SC10U6D3V3MX-DL-GP  [C603H36]  123.18 58.51 90 top
C1138  SC10U6D3V3MX-DL-GP  [C603H36]  113.83 57.42 270 top
C1139  SCD1U16V2KX-3DLGP  [C402H22]  117.18 69.79 180 top
C1140  SCD1U16V2KX-3DLGP  [C402H22]  121.71 69.56 180 top
C1141  SCD1U16V2KX-3DLGP  [C402H22]  113.96 55.64 270 top
C1142  SCD1U16V2KX-3DLGP  [C402H22]  123.23 53.36 90 top
C1201  SCD047U25V2KX-4-GP  [C402H22]  82.62 34.05 90 top
C1202  SCD022U16V2KX-3DLGP  [C402H22]  97.32 32.15 270 top
C1203  SCD047U25V2KX-4-GP  [C402H22]  63.54 34.31 180 top
C1204  SC1U10V2KX-1DLGP  [C402H22]  59.73 44.04 180 top
C1205  SC1U10V2KX-1DLGP  [C402H22]  54.49 43.6 90 top
C1206  SC1U10V2KX-1DLGP  [C402H22]  53.88 42.08 0 top
C1207  SC1U10V2KX-1DLGP  [C402H22]  55.97 38.12 270 top
C1208  SC1U10V2KX-1DLGP  [C402H22]  62.57 31.77 0 top
C1209  SC1U10V2KX-1DLGP  [C402H22]  61.1 40.53 270 top
C1210  SC1U10V2KX-1DLGP  [C402H22]  54.14 37.99 270 top
C1211  SC1U10V2KX-1DLGP  [C402H22]  62.31 36.09 90 top
C1212  SC1U10V2KX-1DLGP  [C402H22]  63.38 42.08 0 top
C1213  SC1U10V2KX-1DLGP  [C402H22]  63.99 43.6 90 top
C1214  SC1U10V2KX-1DLGP  [C402H22]  69.88 44.04 180 top
C1215  SC1U10V2KX-1DLGP  [C402H22]  66.12 38.12 270 top
C1216  SC1U10V2KX-1DLGP  [C402H22]  72.72 31.77 0 top
C1217  SC1U10V2KX-1DLGP  [C402H22]  72.34 36.21 90 top
C1218  SC1U10V2KX-1DLGP  [C402H22]  63.86 36.16 270 top
C1219  SC1U10V2KX-1DLGP  [C402H22]  71.25 40.53 270 top
C1220  SC1U10V2KX-1DLGP  [C402H22]  83.68 42.11 0 top
C1221  SC1U10V2KX-1DLGP  [C402H22]  84.94 43.6 90 top
C1222  SC1U10V2KX-1DLGP  [C402H22]  90.18 44.04 180 top
C1223  SC1U10V2KX-1DLGP  [C402H22]  85.51 31.77 180 top
C1224  SC1U10V2KX-1DLGP  [C402H22]  93.26 39.13 90 top
C1225  SC1U10V2KX-1DLGP  [C402H22]  86.42 38.12 270 top
C1226  SC1U10V2KX-1DLGP  [C402H22]  91.55 40.53 270 top
C1227  SC1U10V2KX-1DLGP  [C402H22]  84.12 36.21 270 top
C1228  SC1U10V2KX-1DLGP  [C402H22]  80.03 44.04 180 top
C1229  SC1U10V2KX-1DLGP  [C402H22]  81.4 40.53 270 top
C1230  SC1U10V2KX-1DLGP  [C402H22]  82.49 36.21 90 top
C1231  SC1U10V2KX-1DLGP  [C402H22]  76.27 38.12 270 top
C1232  SC1U10V2KX-1DLGP  [C402H22]  84.24 33.55 90 top
C1233  SC1U10V2KX-1DLGP  [C402H22]  73.97 36.21 270 top
C1234  SC1U10V2KX-1DLGP  [C402H22]  74.14 43.6 90 top
C1235  SC1U10V2KX-1DLGP  [C402H22]  73.53 42.08 0 top
C1236  SCD047U25V2KX-4-GP  [C402H22]  73.7 34.31 180 top
C1237  SC10U6D3V3MX-DL-GP  [C603H36]  61.25 46.63 180 top
C1238  SC10U6D3V3MX-DL-GP  [C603H36]  57.7 46.63 180 top
C1239  SC10U6D3V3MX-DL-GP  [C603H36]  72.94 46.63 180 top
C1240  SC10U6D3V3MX-DL-GP  [C603H36]  63.16 46.63 180 top
C1241  SC10U6D3V3MX-DL-GP  [C603H36]  93.26 45.61 90 top
C1242  SC10U6D3V3MX-DL-GP  [C603H36]  83.86 46.5 180 top
C1243  SC10U6D3V3MX-DL-GP  [C603H36]  82.59 46.5 180 top
C1244  SC10U6D3V3MX-DL-GP  [C603H36]  74.21 46.63 180 top
C1245  SC10U6D3V3MX-DL-GP  [C603H36]  68.11 61.74 180 top
C1246  SC10U6D3V3MX-DL-GP  [C603H36]  66.84 61.74 180 top
C1255  SC1U10V2KX-1DLGP  [C402H22]  49.19 38.37 270 top
C1256  SCD01U25V2KX-3DLGP  [C402H22]  51.09 39.26 90 top
C1257  SC1U10V2KX-1DLGP  [C402H22]  49.19 37.61 270 top
C1258  SC1U10V2KX-1DLGP  [C402H22]  46.52 38.75 270 top
C1259  SC1U10V2KX-1DLGP  [C402H22]  91.58 42.02 270 top
C1260  SC1U10V2KX-1DLGP  [C402H22]  89.83 28.09 180 bottom
C1261  SC1U10V2KX-1DLGP  [C402H22]  80.43 28.21 180 bottom
C1262  SC1U10V2KX-1DLGP  [C402H22]  71.28 42.02 270 top
C1263  SC1U10V2KX-1DLGP  [C402H22]  64.68 28.21 180 bottom
C1264  SC1U10V2KX-1DLGP  [C402H22]  63.92 28.21 180 bottom
C1265  SC1U10V2KX-1DLGP  [C402H22]  61.13 42.02 270 top
C1266  SC1U10V2KX-1DLGP  [C402H22]  54.4 28.21 180 bottom
C1267  SC1U10V2KX-1DLGP  [C402H22]  53.63 28.21 180 bottom
C1268  SC1U10V2KX-1DLGP  [C402H22]  81.43 42.02 270 top
C1269  SC1U10V2KX-1DLGP  [C402H22]  74.97 28.21 180 bottom
C1270  SC1U10V2KX-1DLGP  [C402H22]  74.21 28.21 180 bottom
C1271  SC1U10V2KX-1DLGP  [C402H22]  92.11 46.63 0 bottom
C1272  SC1U10V2KX-1DLGP  [C402H22]  73.19 46.5 0 bottom
C1273  SC1U10V2KX-1DLGP  [C402H22]  64.94 46.5 0 bottom
C1274  SC1U10V2KX-1DLGP  [C402H22]  82.59 46.5 0 bottom
C1275  SC10U6D3V3MX-DL-GP  [C603H36]  126.12 26.56 270 bottom
C1276  SC10U6D3V3MX-DL-GP  [C603H36]  93.13 46.75 0 bottom
C1277  SC10U6D3V3MX-DL-GP  [C603H36]  74.21 46.63 0 bottom
C1278  SC10U6D3V3MX-DL-GP  [C603H36]  63.16 46.63 0 bottom
C1279  SC10U6D3V3MX-DL-GP  [C603H36]  83.61 46.63 0 bottom
C1280  SC1U10V2KX-1DLGP  [C402H22]  45.63 33.04 270 top
C1281  SC1U10V2KX-1DLGP  [C402H22]  45.63 32.28 270 top
C1282  SC1U10V2KX-1DLGP  [C402H22]  46.52 39.52 270 top
C1283  SC1U10V2KX-1DLGP  [C402H22]  45.63 29.99 270 top
C1284  SC1U10V2KX-1DLGP  [C402H22]  47.41 41.55 270 top
C1285  SC3D3P50V2CN-GP  [C402H22]  87.11 35.83 270 top
C1286  SCD047U25V2KX-4-GP  [C402H22]  95.04 33.42 180 top
C1288  SC10U6D3V3MX-DL-GP  [C603H36]  45.63 37.1 270 top
C1289  SC10U6D3V3MX-DL-GP  [C603H36]  47.16 40.53 270 top
C1290  SC10U6D3V3MX-DL-GP  [C603H36]  51.09 41.04 90 top
C1291  SC10U6D3V3MX-DL-GP  [C603H36]  51.47 43.07 90 top
C1292  SC1U10V2KX-1DLGP  [C402H22]  45.63 34.56 270 top
C1293  SC1U10V2KX-1DLGP  [C402H22]  51.09 40.02 90 top
C1294  SC1U10V2KX-1DLGP  [C402H22]  45.63 33.8 270 top
C1295  SC1U10V2KX-1DLGP  [C402H22]  51.07 42.06 90 top
C1296  SC1U10V2KX-1DLGP  [C402H22]  45.63 31.51 270 top
C1297  SC1U10V2KX-1DLGP  [C402H22]  45.63 30.75 270 top
C1298  SC1U10V2KX-1DLGP  [C402H22]  45.63 36.09 270 top
C1299  SC1U10V2KX-1DLGP  [C402H22]  45.63 35.32 270 top
C1301  SCD047U25V2KX-4-GP  [C402H22]  145.25 34.05 90 top
C1302  SCD022U16V2KX-3DLGP  [C402H22]  103.8 30.75 0 top
C1303  SCD047U25V2KX-4-GP  [C402H22]  134.66 33.67 0 top
C1304  SC1U10V2KX-1DLGP  [C402H22]  144.03 40.53 270 top
C1305  SC1U10V2KX-1DLGP  [C402H22]  142.23 43.68 90 top
C1306  SC1U10V2KX-1DLGP  [C402H22]  137.43 43.6 90 top
C1307  SC1U10V2KX-1DLGP  [C402H22]  136.82 42.08 0 top
C1308  SC1U10V2KX-1DLGP  [C402H22]  137.07 37.61 270 top
C1309  SC1U10V2KX-1DLGP  [C402H22]  145.51 31.77 0 top
C1310  SC1U10V2KX-1DLGP  [C402H22]  145.25 36.09 90 top
C1311  SC1U10V2KX-1DLGP  [C402H22]  144.82 37.61 90 top
C1312  SC1U10V2KX-1DLGP  [C402H22]  124.95 36.09 90 top
C1313  SC1U10V2KX-1DLGP  [C402H22]  123.73 40.53 270 top
C1314  SC1U10V2KX-1DLGP  [C402H22]  118.6 38.12 270 top
C1315  SC1U10V2KX-1DLGP  [C402H22]  122.36 44.04 180 top
C1316  SC1U10V2KX-1DLGP  [C402H22]  116.88 43.6 90 top
C1317  SC1U10V2KX-1DLGP  [C402H22]  116.52 42.08 0 top
C1318  SC1U10V2KX-1DLGP  [C402H22]  125.21 31.77 0 top
C1319  SC1U10V2KX-1DLGP  [C402H22]  117 36.16 270 top
C1320  SC1U10V2KX-1DLGP  [C402H22]  126.67 42.06 0 top
C1321  SC1U10V2KX-1DLGP  [C402H22]  127.28 43.58 90 top
C1322  SC1U10V2KX-1DLGP  [C402H22]  128.75 38.09 270 top
C1323  SC1U10V2KX-1DLGP  [C402H22]  135.36 31.74 0 top
C1324  SC1U10V2KX-1DLGP  [C402H22]  135.1 36.06 90 top
C1325  SC1U10V2KX-1DLGP  [C402H22]  133.88 40.51 270 top
C1326  SC1U10V2KX-1DLGP  [C402H22]  127.15 36.14 270 top
C1327  SC1U10V2KX-1DLGP  [C402H22]  132.51 44.01 180 top
C1328  SC1U10V2KX-1DLGP  [C402H22]  106.97 42.31 270 top
C1329  SC1U10V2KX-1DLGP  [C402H22]  108.24 38.25 270 top
C1330  SC1U10V2KX-1DLGP  [C402H22]  113.56 40.53 270 top
C1331  SC1U10V2KX-1DLGP  [C402H22]  112.19 44.04 180 top
C1332  SC1U10V2KX-1DLGP  [C402H22]  114.77 36.09 90 top
C1333  SC1U10V2KX-1DLGP  [C402H22]  106.97 41.04 270 top
C1334  SC1U10V2KX-1DLGP  [C402H22]  112.31 37.61 0 top
C1335  SC1U10V2KX-1DLGP  [C402H22]  118.61 31.56 90 top
C1336  SCD047U25V2KX-4-GP  [C402H22]  124.7 33.6 0 top
C1337  SC1U10V2KX-1DLGP  [C402H22]  113.71 42.03 270 top
C1338  SC1U10V2KX-1DLGP  [C402H22]  104.05 30.63 90 bottom
C1339  SC1U10V2KX-1DLGP  [C402H22]  115.61 46.5 0 bottom
C1340  SC1U10V2KX-1DLGP  [C402H22]  104.05 31.39 90 bottom
C1341  SC1U10V2KX-1DLGP  [C402H22]  123.86 42 270 top
C1342  SC1U10V2KX-1DLGP  [C402H22]  118.78 28.21 180 bottom
C1343  SCD047U25V2KX-4-GP  [C402H22]  114.34 32.15 270 top
C1344  SC1U10V2KX-1DLGP  [C402H22]  125.9 46.5 0 bottom
C1345  SC1U10V2KX-1DLGP  [C402H22]  119.55 28.21 180 bottom
C1346  SC1U10V2KX-1DLGP  [C402H22]  133.88 42 270 top
C1347  SC1U10V2KX-1DLGP  [C402H22]  126.91 28.21 180 bottom
C1348  SC1U10V2KX-1DLGP  [C402H22]  126.15 28.21 180 bottom
C1349  SC1U10V2KX-1DLGP  [C402H22]  134.02 46.5 0 bottom
C1350  SC1U10V2KX-1DLGP  [C402H22]  137.58 28.72 180 bottom
C1351  SC1U10V2KX-1DLGP  [C402H22]  144.11 42.06 270 top
C1352  SC1U10V2KX-1DLGP  [C402H22]  136.82 28.72 180 bottom
C1353  SC1U10V2KX-1DLGP  [C402H22]  145.07 46.5 0 bottom
C1354  SC1U10V2KX-1DLGP  [C402H22]  154.34 37.74 270 bottom
C1355  SC1U10V2KX-1DLGP  [C402H22]  152.44 39.64 0 bottom
C1356  SC1U10V2KX-1DLGP  [C402H22]  151.68 39.64 0 bottom
C1357  SC1U10V2KX-1DLGP  [C402H22]  148.63 29.48 90 bottom
C1358  SC1U10V2KX-1DLGP  [C402H22]  154.34 30.12 270 bottom
C1359  SC1U10V2KX-1DLGP  [C402H22]  150.92 39.64 0 bottom
C1360  SC1U10V2KX-1DLGP  [C402H22]  150.15 39.64 0 bottom
C1361  SC1U10V2KX-1DLGP  [C402H22]  154.34 36.21 270 bottom
C1362  SC1U10V2KX-1DLGP  [C402H22]  154.34 36.98 270 bottom
C1363  SC1U10V2KX-1DLGP  [C402H22]  154.34 33.93 270 bottom
C1364  SC1U10V2KX-1DLGP  [C402H22]  154.34 33.17 270 bottom
C1365  SC1U10V2KX-1DLGP  [C402H22]  154.34 32.4 270 bottom
C1366  SC1U10V2KX-1DLGP  [C402H22]  154.34 30.88 270 bottom
C1367  SC1U10V2KX-1DLGP  [C402H22]  154.34 31.64 270 bottom
C1368  SC1U10V2KX-1DLGP  [C402H22]  154.34 35.45 270 bottom
C1369  SC1U10V2KX-1DLGP  [C402H22]  154.34 34.69 270 bottom
C1370  SCD01U25V2KX-3DLGP  [C402H22]  145.78 40.53 270 top
C1371  SC10U6D3V3MX-DL-GP  [C603H36]  114.59 46.37 0 bottom
C1372  SC10U6D3V3MX-DL-GP  [C603H36]  126.12 25.16 270 bottom
C1373  SC10U6D3V3MX-DL-GP  [C603H36]  124.88 46.5 0 bottom
C1374  SC10U6D3V3MX-DL-GP  [C603H36]  133.01 46.63 0 bottom
C1375  SC10U6D3V3MX-DL-GP  [C603H36]  144.06 46.63 0 bottom
C1376  SC10U6D3V3MX-DL-GP  [C603H36]  154.09 27.83 270 bottom
C1377  SC10U6D3V3MX-DL-GP  [C603H36]  154.09 38.88 270 bottom
C1378  SC10U6D3V3MX-DL-GP  [C603H36]  154.09 29.1 270 bottom
C1379  SC10U6D3V3MX-DL-GP  [C603H36]  148.63 28.34 90 bottom
C1388  SC3D3P50V2CN-GP  [C402H22]  109.23 35.83 270 top
C1390  SC10U6D3V3MX-DL-GP  [C603H36]  139.36 46.25 180 top
C1391  SC10U6D3V3MX-DL-GP  [C603H36]  145.07 44.85 180 top
C1392  SC10U6D3V3MX-DL-GP  [C603H36]  116.63 44.72 90 top
C1393  SC10U6D3V3MX-DL-GP  [C603H36]  125.13 46.5 180 top
C1394  SC10U6D3V3MX-DL-GP  [C603H36]  133.14 46.25 180 top
C1395  SC10U6D3V3MX-DL-GP  [C603H36]  126.53 46.5 180 top
C1396  SC10U6D3V3MX-DL-GP  [C603H36]  112.94 45.61 270 top
C1397  SC10U6D3V3MX-DL-GP  [C603H36]  67.22 56.53 0 top
C1398  SC10U6D3V3MX-DL-GP  [C603H36]  65.95 56.53 0 top
C1399  SC10U6D3V3MX-DL-GP  [C603H36]  109.89 45.36 270 top
C1701  SC220P50V2KX-3DLGP  [C402H22]  140.37 52.65 270 top
C1710  SCD47U10V2KX-1-GP  [C402H22]  19.85 14.27 270 bottom
C1711  SCD1U16V2KX-3DLGP  [C402H22]  52.24 81.55 90 bottom
C1803  SC15P50V2JN-DL-GP  [C402H22]  127.62 55.49 90 top
C1804  SC15P50V2JN-DL-GP  [C402H22]  126.1 55.49 90 top
C1805  SC1U10V2KX-1DLGP  [C402H22]  140.78 47.36 180 bottom
C1806  SC1U10V2KX-1DLGP  [C402H22]  138.6 49.52 180 bottom
C1807  SC15P50V2JN-DL-GP  [C402H22]  138.72 93.79 90 bottom
C1808  SC15P50V2JN-DL-GP  [C402H22]  137.22 93.79 270 bottom
C2201  SCD1U16V2KX-3DLGP  [C402H22]  126.2 74.29 0 top
C2202  SC1U10V2KX-1DLGP  [C402H22]  132.7 75.84 180 top
C2203  SC1U10V2KX-1DLGP  [C402H22]  135.83 72.36 0 top
C2204  SC1U10V2KX-1DLGP  [C402H22]  136.59 72.36 0 top
C2205  SC1U10V2KX-1DLGP  [C402H22]  137.35 72.41 0 top
C2206  SCD1U16V2KX-3DLGP  [C402H22]  138.11 72.41 0 top
C2207  SCD1U16V2KX-3DLGP  [C402H22]  138.55 71.27 270 top
C2208  SC22U6D3V3MX-1-DL-GP  [C603H40]  127.67 94.38 90 bottom
C2209  SC1U10V2KX-1DLGP  [C402H22]  127.67 93.24 90 bottom
C2210  SC1U10V2KX-1DLGP  [C402H22]  132.12 78.83 270 top
C2211  SC1U10V2KX-1DLGP  [C402H22]  133.29 79.44 180 top
C2212  SC1U10V2KX-1DLGP  [C402H22]  132.58 80.59 90 top
C2213  SC1U10V2KX-1DLGP  [C402H22]  129.15 73.86 90 top
C2214  SC1U10V2KX-1DLGP  [C402H22]  161.33 71.72 90 bottom
C2215  SC1U10V2KX-1DLGP  [C402H22]  158.79 93.95 0 bottom
C2216  SC1U10V2KX-1DLGP  [C402H22]  165.52 77.36 270 bottom
C2217  SC1U10V2KX-1DLGP  [C402H22]  164.76 76.6 270 bottom
C2218  SC4D7U6D3V3KX-DLGP  [C603H36]  140.6 72.13 270 top
C2219  SC1U10V2KX-1DLGP  [C402H22]  142.79 95.01 0 bottom
C2220  SC22U6D3V3MX-1-DL-GP  [C603H40]  153.2 79.6 90 top
C2221  SCD1U16V2KX-3DLGP  [C402H22]  153.33 65.8 270 top
C2222  SC1U10V2KX-1DLGP  [C402H22]  153.33 66.59 270 top
C2223  SC1U10V2KX-1DLGP  [C402H22]  125.52 76.09 180 top
C2224  SC1U10V2KX-1DLGP  [C402H22]  153.91 71.47 0 bottom
C2405  SC100P50V2JN-3DLGP  [C402H22]  25.67 12.39 180 bottom
C2406  SCD1U16V2KX-3DLGP  [C402H22]  22.39 13.99 0 bottom
C2407  SCD1U16V2KX-3DLGP  [C402H22]  20.11 18.81 90 bottom
C2408  SCD1U16V2KX-3DLGP  [C402H22]  23.79 21.1 270 top
C2409  SCD01U25V2KX-3DLGP  [C402H22]  35.45 32.66 0 bottom
C2410  SCD1U16V2KX-3DLGP  [C402H22]  32.81 29.1 270 top
C2411  SCD1U16V2KX-3DLGP  [C402H22]  23.92 23.77 270 top
C2412  SCD1U16V2KX-3DLGP  [C402H22]  27.09 32.4 0 bottom
C2413  SCD1U16V2KX-3DLGP  [C402H22]  41.31 14.75 270 bottom
C2414  SCD1U16V2KX-3DLGP  [C402H22]  26.33 32.4 0 bottom
C2416  SCD1U16V2KX-3DLGP  [C402H22]  46.14 22.37 270 bottom
C2418  SC1U10V2KX-1DLGP  [C402H22]  31.92 32.66 0 bottom
C2420  SCD1U16V2KX-3DLGP  [C402H22]  30.39 12.85 90 bottom
C2421  SCD1U16V2KX-3DLGP  [C402H22]  46.14 21.61 270 bottom
C2422  SCD1U16V2KX-3DLGP  [C402H22]  20.13 17.21 90 bottom
C2423  SCD1U16V2KX-3DLGP  [C402H22]  34.61 19.42 270 top
C2424  SC18P50V2JN-1DLGP  [C402H22]  21.5 27.2 0 bottom
C2425  SC18P50V2JN-1DLGP  [C402H22]  21.5 25.67 180 bottom
C2427  SC2D2U10V3KX-1DLGP-U  [C603H36]  22.26 29.76 0 bottom
C2428  SCD1U16V2KX-3DLGP  [C402H22]  23.74 26.41 90 top
C2429  SCD1U16V2KX-3DLGP  [C402H22]  32.81 29.99 270 top
C2435  SC2200P50V2KX-2DLGP  [C402H22]  21.22 20.16 0 bottom
C2436  SC2200P50V2KX-2DLGP  [C402H22]  26.96 22.75 90 top
C2441  SC2200P50V2KX-2DLGP  [C402H22]  21.5 21.86 180 bottom
C2501  SC10U6D3V3MX-DL-GP  [C603H36]  143.68 57.96 0 top
C2502  SCD1U16V2KX-3DLGP  [C402H22]  142.3 58.18 180 bottom
C2503  SCD47U25V3KX-1-DL-GP  [C603H36]  185.05 37.61 180 bottom
C2517  SCD022U16V2KX-3DLGP  [C402H22]  187.52 65.6 90 top
C2525  SC1U10V2KX-1DLGP  [C402H22]  160.57 69.23 270 bottom
C2601  SC10U6D3V3MX-DL-GP  [C603H36]  40.04 37.23 90 bottom
C2602  SCD1U16V2KX-3DLGP  [C402H22]  43.22 29.86 0 bottom
C2603  SC2200P50V2KX-2DLGP  [C402H22]  188.25 72.15 90 bottom
C2604  SC4D7U6D3V3KX-DLGP  [C603H36]  187.87 68.6 90 bottom
C2605  SCD1U16V2KX-3DLGP  [C402H22]  188.25 71.39 90 bottom
C2606  SC470P50V3JN-2GP  [C603H36]  72.81 94.63 0 top
C2607  SC2200P50V2KX-2DLGP  [C402H22]  42.2 36.98 270 bottom
C2608  SCD1U16V2KX-3DLGP  [C402H22]  38.82 31.08 90 bottom
C2609  SCD1U16V2KX-3DLGP  [C402H22]  39.54 33.93 0 bottom
C2610  SCD1U16V2KX-3DLGP  [C402H22]  21.25 7.89 180 bottom
C2612  SCD1U16V2KX-3DLGP  [C402H22]  164.35 66.59 180 bottom
C2613  SC100P50V2JN-3DLGP  [C402H22]  28.87 26.43 0 top
C2614  SCD1U16V2KX-3DLGP  [C402H22]  24.8 10.81 0 bottom
C2714  SCD1U16V2KX-3DLGP  [C402H22]  174.16 17.04 180 top
C2721  SCD1U16V2KX-3DLGP  [C402H22]  177.84 13.99 180 bottom
C2722  SCD1U16V2KX-3DLGP  [C402H22]  168.82 16.78 90 bottom
C2726  SCD1U16V2KX-3DLGP  [C402H22]  180.56 15.79 90 bottom
C2727  SC10U6D3V3MX-DL-GP  [C603H36]  178.7 14.17 90 top
C2729  SCD1U16V2KX-3DLGP  [C402H22]  168.82 16.02 270 bottom
C2730  SC10U6D3V3MX-DL-GP  [C603H36]  177.2 24.66 90 top
C2731  SC10U6D3V2MX-2-GP  [C402-TO0D2H28]  179.49 13.99 0 bottom
C2732  SC10U6D3V3MX-DL-GP  [C603H36]  173.09 17.16 180 top
C2733  SC10U6D3V3MX-DL-GP  [C603H36]  175.17 16.91 180 top
C2734  SC10U6D3V2MX-2-GP  [C402-TO0D2H28]  177.46 24.58 180 bottom
C2735  SC10U6D3V2MX-2-GP  [C402-TO0D2H28]  181.67 18.36 270 bottom
C2736  SC10U6D3V2MX-2-GP  [C402-TO0D2H28]  175.55 24.53 0 bottom
C2737  SC2D2U10V3KX-1DLGP-U  [C603H36]  181.19 14.78 90 bottom
C2739  SC1U25V3KX-1-DLGP  [C603H36]  179.13 24.71 90 bottom
C2740  SCD1U16V2KX-3DLGP  [C402H22]  176.44 24.53 180 bottom
C2741  SC1U25V3KX-1-DLGP  [C603H36]  181.5 24.25 270 bottom
C2742  SCD1U16V2KX-3DLGP  [C402H22]  176.19 16.78 180 top
C2743  SC10U6D3V2MX-2-GP  [C402-TO0D2H28]  168.7 15.13 90 bottom
C2744  SCD1U16V2KX-3DLGP  [C402H22]  174.03 23.77 270 top
C2745  SC10U6D3V3MX-DL-GP  [C603H36]  173.9 24.78 270 top
C2746  SCD1U16V2KX-3DLGP  [C402H22]  170.73 15 0 bottom
C2907  SC10U6D3V3MX-DL-GP  [C603H36]  176.82 34.33 180 top
C2908  SC10U6D3V3MX-DL-GP  [C603H36]  179.24 35.32 180 top
C2909  SC10U6D3V3MX-DL-GP  [C603H36]  178.58 31.87 90 top
C4001  SC470P50V2KX-3DLGP  [C402H22]  72.4 24.96 0 bottom
C4002  SC470P50V2KX-3DLGP  [C402H22]  71.59 24.96 0 bottom
C4003  SCD22U10V2KX-1GP  [C402H22]  72.05 21.35 0 top
C4004  SC10U25V5KX-DL-GP  [C805H58]  67.22 24.4 90 bottom
C4005  SC10U25V5KX-DL-GP  [C805H58]  77.13 24.4 270 bottom
C4006  SC10U6D3V3MX-DL-GP  [C603H36]  177.2 59.07 270 top
C4007  SCD1U16V2KX-3DLGP  [C402H22]  175.81 62.76 180 top
C4008  SC10U6D3V3MX-DL-GP  [C603H36]  151.17 67.46 90 bottom
C4009  SC2D2U10V3KX-1DLGP-U  [C603H36]  93.26 14.5 90 top
C4010  SCD1U16V2KX-3DLGP  [C402H22]  155.46 63.75 270 bottom
C4012  SC10U6D3V3MX-DL-GP  [C603H36]  150.66 92.73 180 bottom
C4013  SC10U6D3V3MX-DL-GP  [C603H36]  157.01 94.43 0 bottom
C4031  SC1U10V2KX-1DLGP  [C402H22]  155.74 91.97 180 bottom
C4032  SC1U10V2KX-1DLGP  [C402H22]  180 66.06 180 top
C4034  SCD1U16V2KX-3DLGP  [C402H22]  153.58 91.46 90 bottom
C4035  SC1U10V2KX-1DLGP  [C402H22]  177.33 60.09 270 top
C4037  SCD1U16V2KX-3DLGP  [C402H22]  173.65 10.69 90 bottom
C4038  SC1U10V2KX-1DLGP  [C402H22]  173.6 7.71 270 bottom
C4039  SCD1U16V2KX-3DLGP  [C402H22]  176.19 7.13 270 top
C4040  SCD1U16V2KX-3DLGP  [C402H22]  156.3 68.12 0 bottom
C4041  SC22U6D3V3MX-1-DL-GP  [C603H40]  151.17 68.73 90 bottom
C4042  SC22U6D3V3MX-1-DL-GP  [C603H40]  151.17 66.19 90 bottom
C4043  SC1U10V2KX-1DLGP  [C402H22]  154.98 68.47 270 bottom
C4301  SC1U25V3KX-1-DLGP  [C603H36]  45.76 83.84 180 bottom
C4302  SCD1U25V2KX-1-DL-GP  [C402H22]  45.78 87.39 0 bottom
C4303  SCD01U25V2KX-3DLGP  [C402H22]  40.93 81.55 180 bottom
C4304  SCD01U50V2KX-1DLGP  [C402H22]  39.41 86.38 0 bottom
C4305  SCD01U50V2KX-1DLGP  [C402H22]  38.65 86.38 0 bottom
C4306  SC10U25V5KX-DL-GP  [C805H58]  36.69 84.7 90 bottom
C4343  SC1500P50V2KX-2-DL-GP  [C402H22]  36.62 78.5 90 bottom
C4344  SC1KP50V2KX-1DLGP  [C402H22]  20.36 44.21 90 bottom
C5501  SCD1U16V2KX-3DLGP  [C402H22]  93.64 101.45 180 top
C5502  SC10U6D3V3MX-DL-GP  [C603H36]  75.86 102.51 0 bottom
C5503  SC4D7U6D3V3KX-DLGP  [C603H36]  104.69 99.59 90 top
C5504  SCD1U16V2KX-3DLGP  [C402H22]  94.4 101.45 180 top
C5506  SCD1U16V2KX-3DLGP  [C402H22]  95.42 101.49 180 top
C5507  SCD1U16V2KX-3DLGP  [C402H22]  102.71 99.38 270 top
C5508  SC1U10V2KX-1DLGP  [C402H22]  102.71 98.62 270 top
C5509  SCD1U16V2KX-3DLGP  [C402H22]  96.18 101.49 180 top
C5510  SCD1U16V2KX-3DLGP  [C402H22]  89.07 99.93 180 top
C5511  SCD1U16V2KX-3DLGP  [C402H22]  89.83 99.93 180 top
C5512  SCD1U25V2KX-1-DL-GP  [C402H22]  80.18 97.55 0 bottom
C5513  SC1KP50V2KX-1DLGP  [C402H22]  81.19 97.55 0 bottom
C5514  SC10U25V5KX-DL-GP  [C805H58]  80.68 95.01 180 bottom
C5515  SC4D7U6D3V3KX-DLGP  [C603H36]  121.07 99.46 270 top
C5516  SCD1U25V2KX-1-DL-GP  [C402H22]  134.28 99.08 0 top
C5517  SC10U6D3V3MX-DL-GP  [C603H36]  135.55 99.33 0 top
C5518  SC10U6D3V3MX-DL-GP  [C603H36]  133.01 99.33 0 top
C5519  SCD1U16V2KX-3DLGP  [C402H22]  92.5 101.45 180 top
C5521  SC4D7U6D3V3KX-DLGP  [C603H36]  111.34 98.7 90 top
C5531  SCD1U16V2KX-3DLGP  [C402H22]  91.35 99.93 180 top
C5532  SCD1U16V2KX-3DLGP  [C402H22]  90.59 99.93 180 top
C5533  SCD1U16V2KX-3DLGP  [C402H22]  91.73 101.45 180 top
C5535  SC1U10V2KX-1DLGP  [C402H22]  145.56 101.54 180 bottom
C5724  SCD75P50V1CN-GP  [C0201H13]  19.22 88.92 180 top
C5726  SCD1U16V2KX-3DLGP  [C402H22]  34.84 84.22 180 bottom
C5727  SCD1U16V2KX-3DLGP  [C402H22]  29.44 87.66 270 top
C5728  SCD1U16V2KX-3DLGP  [C402H22]  29.44 86.9 270 top
C5729  SC20P50V2JN-1-DL-GP  [C402H22]  21.98 80.13 0 top
C5730  SC20P50V2JN-1-DL-GP  [C402H22]  18.78 81.09 270 top
C5731  SCD1U16V2KX-3DLGP  [C402H22]  29.44 84.46 270 top
C5732  SCD1U16V2KX-3DLGP  [C402H22]  29.44 85.37 270 top
C5733  SCD1U16V2KX-3DLGP  [C402H22]  29.44 89.18 270 top
C5734  SCD1U16V2KX-3DLGP  [C402H22]  29.44 86.14 270 top
C5735  SCD1U16V2KX-3DLGP  [C402H22]  29.44 88.42 270 top
C5736  SCD1U16V2KX-3DLGP  [C402H22]  15.91 96.28 0 top
C5737  SCD1U16V2KX-3DLGP  [C402H22]  29.44 83.7 270 top
C5738  SCD1U16V2KX-3DLGP  [C402H22]  26.25 76.14 180 top
C5739  SCD1U16V2KX-3DLGP  [C402H22]  25.49 76.14 180 top
C5740  SCD1U16V2KX-3DLGP  [C402H22]  25.82 80.23 180 top
C5741  SCD1U16V2KX-3DLGP  [C402H22]  25.06 80.23 180 top
C5742  SC10U6D3V3MX-DL-GP  [C603H36]  34.15 80.84 0 bottom
C5743  SC1U10V2KX-1DLGP  [C402H22]  34.35 77.67 270 bottom
C5744  SCD1U16V2KX-3DLGP  [C402H22]  31.81 74.34 90 bottom
C5745  SC68P50V2JN-1DLGP  [C402H22]  26.38 78.45 180 bottom
C5746  SC10U6D3V3MX-DL-GP  [C603H36]  28.61 78.89 0 top
C5747  SC10U6D3V3MX-DL-GP  [C603H36]  27.34 78.89 0 top
C5748  SCD47U25V3KX-1-DL-GP  [C603H36]  18.33 93.36 90 top
C5749  SC10U6D3V3MX-DL-GP  [C603H36]  18.2 90.82 270 top
C5750  SCD1U16V2KX-3DLGP  [C402H22]  20.08 87.57 90 bottom
C5751  SCD1U16V2KX-3DLGP  [C402H22]  20.08 86.81 90 bottom
C5752  SCD1U16V2KX-3DLGP  [C402H22]  27.34 88.92 270 bottom
C5753  SCD47U10V2KX-1-GP  [C402H22]  23.53 77.34 180 bottom
C5754  SC10U6D3V2MX-2-GP  [C402-TO0D2H28]  23 86.53 0 bottom
C5755  SCD1U16V2KX-3DLGP  [C402H22]  24.93 83.84 180 bottom
C5756  SCD1U16V2KX-3DLGP  [C402H22]  24.17 83.84 180 bottom
C5757  SCD01U25V2KX-3DLGP  [C402H22]  23.41 83.84 180 bottom
C5758  SCD01U25V2KX-3DLGP  [C402H22]  22.65 83.84 180 bottom
C5759  SCD47U10V2KX-1-GP  [C402H22]  22.01 77.34 180 bottom
C5760  SC10U6D3V2MX-2-GP  [C402-TO0D2H28]  21.71 88.08 90 bottom
C5761  SCD1U16V2KX-3DLGP  [C402H22]  22.34 90.01 0 bottom
C5762  SCD01U25V2KX-3DLGP  [C402H22]  21.55 90.01 0 bottom
C5763  SCD47U10V2KX-1-GP  [C402H22]  22.77 77.34 180 bottom
C5764  SC10U6D3V3MX-DL-GP  [C603H36]  30.77 79.29 90 top
C5765  SCD1U16V2KX-3DLGP  [C402H22]  29.45 80.46 90 top
C5766  SCD1U16V2KX-3DLGP  [C402H22]  29.45 82.01 90 top
C5767  SCD1U16V2KX-3DLGP  [C402H22]  29.45 81.22 90 top
C5768  SCD01U25V2KX-3DLGP  [C402H22]  26.07 84.22 90 bottom
C5769  SCD01U25V2KX-3DLGP  [C402H22]  26.07 83.46 90 bottom
C5770  SCD01U25V2KX-3DLGP  [C402H22]  26.15 85.51 90 bottom
C5771  SCD47U10V2KX-1-GP  [C402H22]  21.2 79.01 0 bottom
C5772  SC10U6D3V2MX-2-GP  [C402-TO0D2H28]  20.08 82.87 90 bottom
C5773  SCD1U16V2KX-3DLGP  [C402H22]  20.08 86.05 90 bottom
C5774  SCD1U16V2KX-3DLGP  [C402H22]  20.08 84.52 90 bottom
C5775  SCD01U25V2KX-3DLGP  [C402H22]  20.08 83.76 90 bottom
C5776  SCD01U25V2KX-3DLGP  [C402H22]  20.08 85.29 90 bottom
C5777  SCD1U16V2KX-3DLGP  [C402H22]  36.26 85.03 90 top
C5778  SC1U25V3KX-1-DLGP  [C603H36]  31.43 81.5 0 top
C6101  SCD1U16V2KX-3DLGP  [C402H22]  169.33 61.99 0 top
C6102  SCD1U16V2KX-3DLGP  [C402H22]  170.09 67.2 180 top
C6103  SCD1U16V2KX-3DLGP  [C402H22]  169.2 67.2 180 top
C6104  SCD1U16V2KX-3DLGP  [C402H22]  167.27 44.47 90 top
C6105  SC10U6D3V3MX-DL-GP  [C603H36]  167.04 66.82 90 bottom
C6106  SCD1U16V2KX-3DLGP  [C402H22]  170.09 61.99 0 top
C6107  SCD1U16V2KX-3DLGP  [C402H22]  154.6 56.25 0 bottom
C6108  SCD1U16V2KX-3DLGP  [C402H22]  155.36 56.25 0 bottom
C6302  SCD22U10V2KX-2-GP  [C402H22]  183.6 10.53 90 bottom
C6303  SCD22U10V2KX-2-GP  [C402H22]  183.6 11.3 90 bottom
C6304  SC33P50V2JN-3DLGP  [C402H22]  191.3 19.45 270 top
C6305  SC33P50V2JN-3DLGP  [C402H22]  191.3 20.21 270 top
C6306  SCD047U25V2KX-4-GP  [C402H22]  192.44 5.1 270 top
C6307  SCD1U16V2KX-3DLGP  [C402H22]  191.3 20.97 270 top
C6308  SCD047U25V2KX-4-GP  [C402H22]  192.44 5.86 270 top
C6309  SCD1U16V2KX-3DLGP  [C402H22]  153.58 4.34 270 top
C6310  SCD047U25V2KX-4-GP  [C402H22]  153.58 5.1 270 top
C6311  SCD22U10V2KX-2-GP  [C402H22]  185.38 13.58 90 bottom
C6312  SCD22U10V2KX-2-GP  [C402H22]  185.38 14.34 90 bottom
C6313  SCD22U10V2KX-2-GP  [C402H22]  185.38 16.5 90 bottom
C6314  SCD22U10V2KX-2-GP  [C402H22]  185.38 17.26 90 bottom
C6315  SCD22U10V2KX-2-GP  [C402H22]  185.26 19.55 90 bottom
C6316  SCD22U10V2KX-2-GP  [C402H22]  185.26 20.31 90 bottom
C6317  SC22U6D3V3MX-1-DL-GP  [C603H40]  191.43 9.42 270 top
C6318  SC22U6D3V3MX-1-DL-GP  [C603H40]  191.81 18.43 270 top
C6319  SCD047U25V2KX-4-GP  [C402H22]  153.58 5.86 270 top
C6320  SC10U6D3V3MX-DL-GP  [C603H36]  153.2 6.88 270 top
C6321  SC33P50V2JN-3DLGP  [C402H22]  153.2 21.86 180 top
C6322  SC33P50V2JN-3DLGP  [C402H22]  153.96 21.86 180 top
C6323  SC10U6D3V3MX-DL-GP  [C603H36]  152.19 21.86 180 top
C6324  SCD22U10V2KX-2-GP  [C402H22]  151.5 15.51 270 top
C6325  SCD22U10V2KX-2-GP  [C402H22]  151.5 14.75 270 top
C6326  SCD22U10V2KX-2-GP  [C402H22]  153.76 12.46 270 top
C6327  SCD22U10V2KX-2-GP  [C402H22]  153.76 11.7 270 top
C6401  SCD1U16V2KX-3GP  [C402H22]  34.58 22.5 180 top
C6501  SCD1U16V2KX-3DLGP  [C402H22]  70.91 13.73 90 bottom
C6502  SCD1U16V2KX-3DLGP  [C402H22]  83.53 13.12 0 bottom
C6504  SCD1U16V2KX-3DLGP  [C402H22]  72.68 14.12 0 bottom
C6505  SCD1U16V2KX-3DLGP  [C402H22]  80.94 9.29 270 top
C6506  SCD1U16V2KX-3DLGP  [C402H22]  70.91 14.5 90 bottom
C6605  SCD1U16V2KX-3DLGP  [C402H22]  176.8 43.63 90 top
C7101  SCD1U16V2KX-3DLGP  [C402H22]  19.24 74.34 180 top
C7102  SCD1U16V2KX-3DLGP  [C402H22]  18.48 74.34 180 top
C7103  SCD1U16V2KX-3DLGP  [C402H22]  21.76 63.42 180 top
C7104  SCD1U16V2KX-3DLGP  [C402H22]  20.94 63.42 180 top
C7105  SCD1U16V2KX-3DLGP  [C402H22]  20.16 63.42 180 top
C7106  SCD1U16V2KX-3DLGP  [C402H22]  19.37 63.42 180 top
C7107  SCD1U16V2KX-3DLGP  [C402H22]  23.56 67.81 270 top
C7108  SCD1U16V2KX-3DLGP  [C402H22]  23.58 69.69 270 top
C7109  SCD1U16V2KX-3DLGP  [C402H22]  23.58 68.93 270 top
C7110  SCD1U16V2KX-3DLGP  [C402H22]  23.61 71.52 270 top
C7111  SCD1U16V2KX-3DLGP  [C402H22]  23.61 70.76 270 top
C7112  SCD1U16V2KX-3DLGP  [C402H22]  23.25 64.81 270 top
C7113  SCD1U16V2KX-3DLGP  [C402H22]  23.25 65.58 270 top
C7114  SCD1U16V2KX-3DLGP  [C402H22]  23.56 67.05 270 top
C7115  SCD1U16V2KX-3DLGP  [C402H22]  16.4 64.64 90 top
C7116  SCD1U16V2KX-3DLGP  [C402H22]  15.79 72.41 90 top
C7117  SCD1U16V2KX-3DLGP  [C402H22]  23.61 72.38 270 top
C7118  SCD1U16V2KX-3DLGP  [C402H22]  20.11 64.03 0 bottom
C7119  SC10U6D3V3MX-DL-GP  [C603H36]  23.41 63.52 90 top
C7120  SCD33U6D3V2KX-1-GP  [C402H22]  12.08 71.39 270 top
C7121  SCD33U6D3V2KX-1-GP  [C402H22]  12.08 70.63 270 top
C7122  SCD33U6D3V2KX-1-GP  [C402H22]  12.13 66.49 270 top
C7123  SCD33U6D3V2KX-1-GP  [C402H22]  12.13 65.73 270 top
C7161  SCD1U25V2KX-1-DL-GP  [C402H22]  15.51 67.35 90 top
C7162  SCD1U25V2KX-1-DL-GP  [C402H22]  15.51 68.12 90 top
C7163  SCD1U25V2KX-1-DL-GP  [C402H22]  15.56 68.98 90 top
C7164  SCD1U25V2KX-1-DL-GP  [C402H22]  15.56 69.74 90 top
